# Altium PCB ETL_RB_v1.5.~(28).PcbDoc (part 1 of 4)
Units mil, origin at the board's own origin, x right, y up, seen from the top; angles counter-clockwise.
Board outline 5129.92 x 2224.41 mil, 8 copper layers (Top Layer, plane 1, M1, plane 2, plane 3, M2, plane 4, Bottom Layer), stack 36.907 mil thick; 212 components, 186 nets, 1961 pads, 978 vias.
Unrouted connection lines stored in the file: 395.
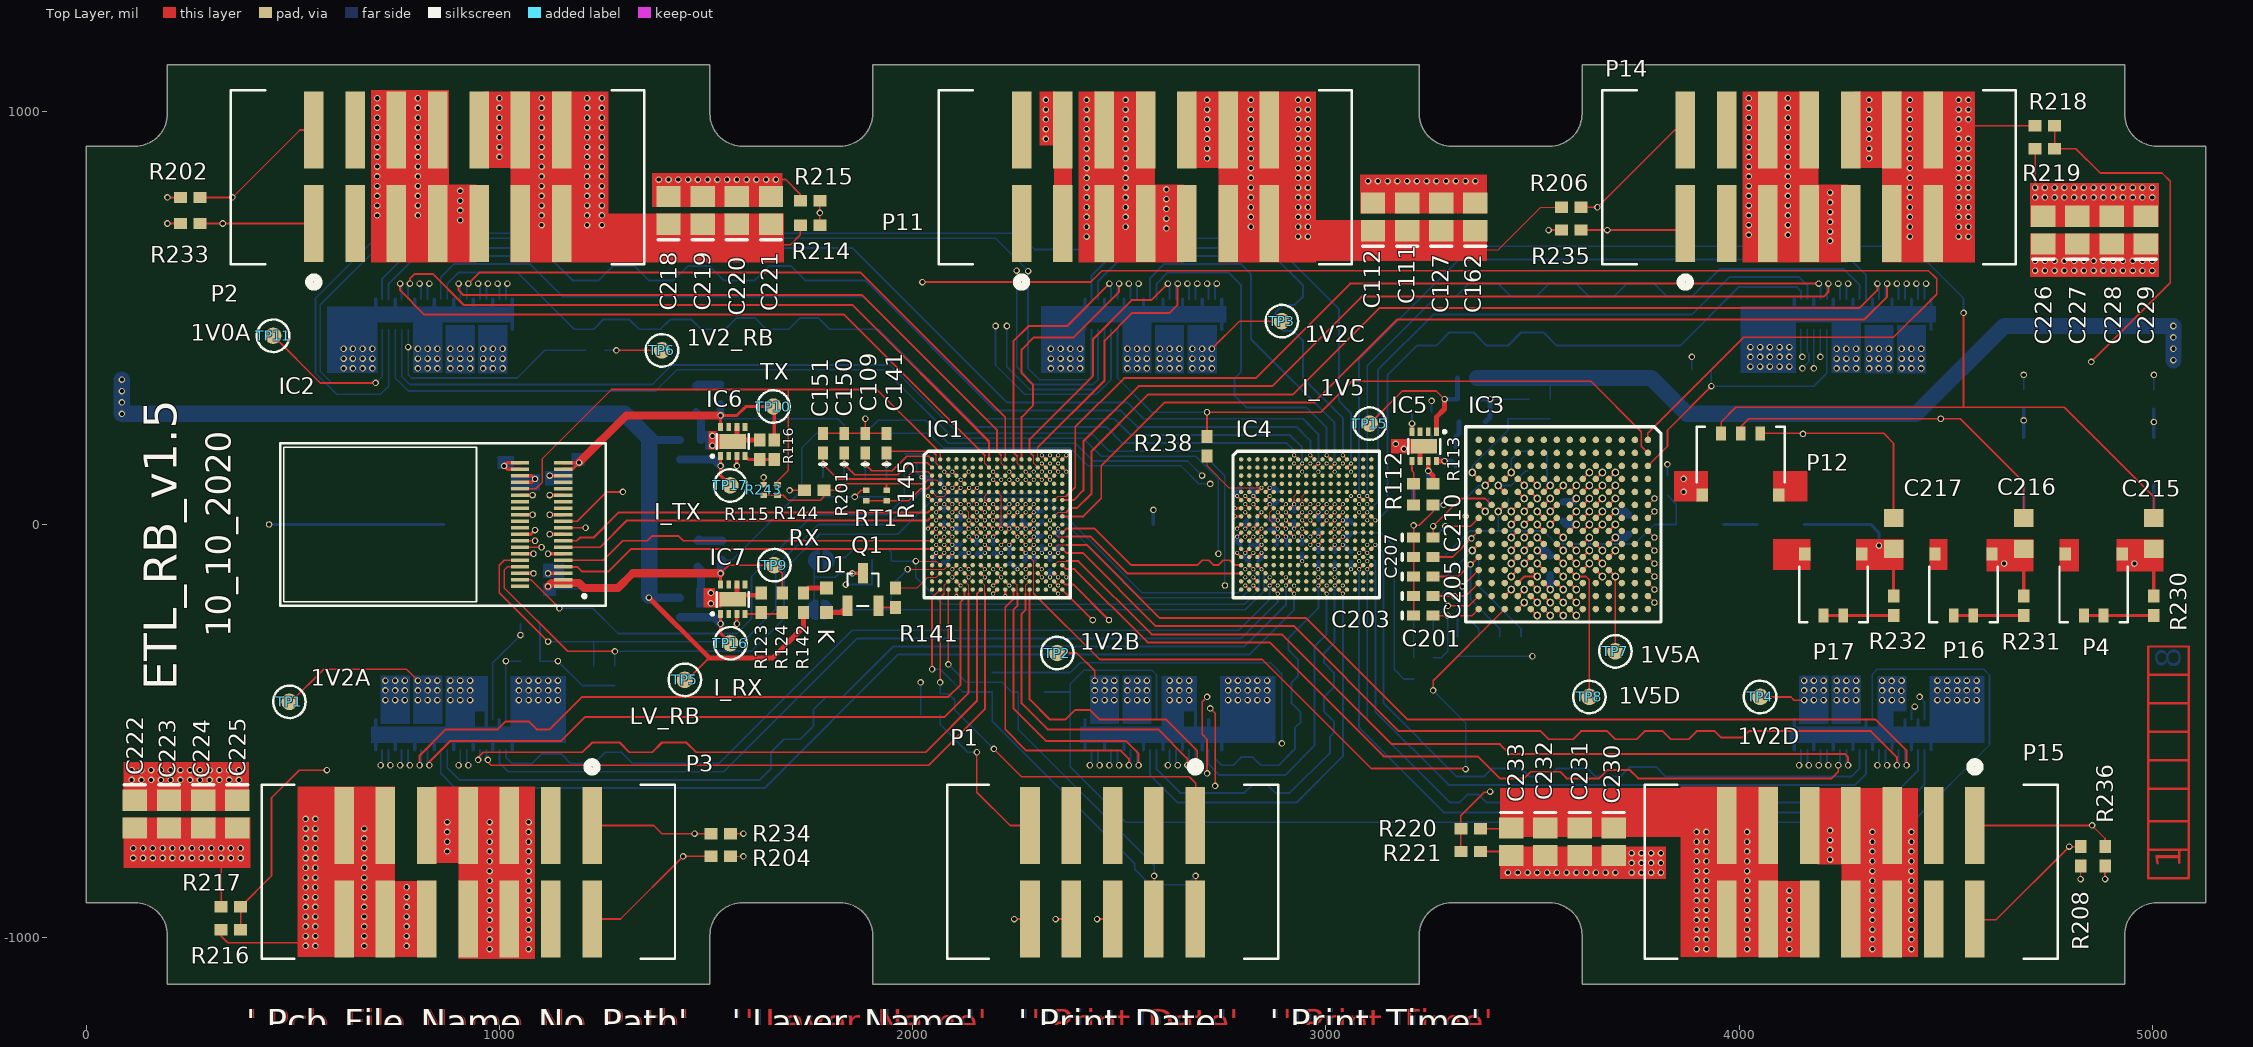
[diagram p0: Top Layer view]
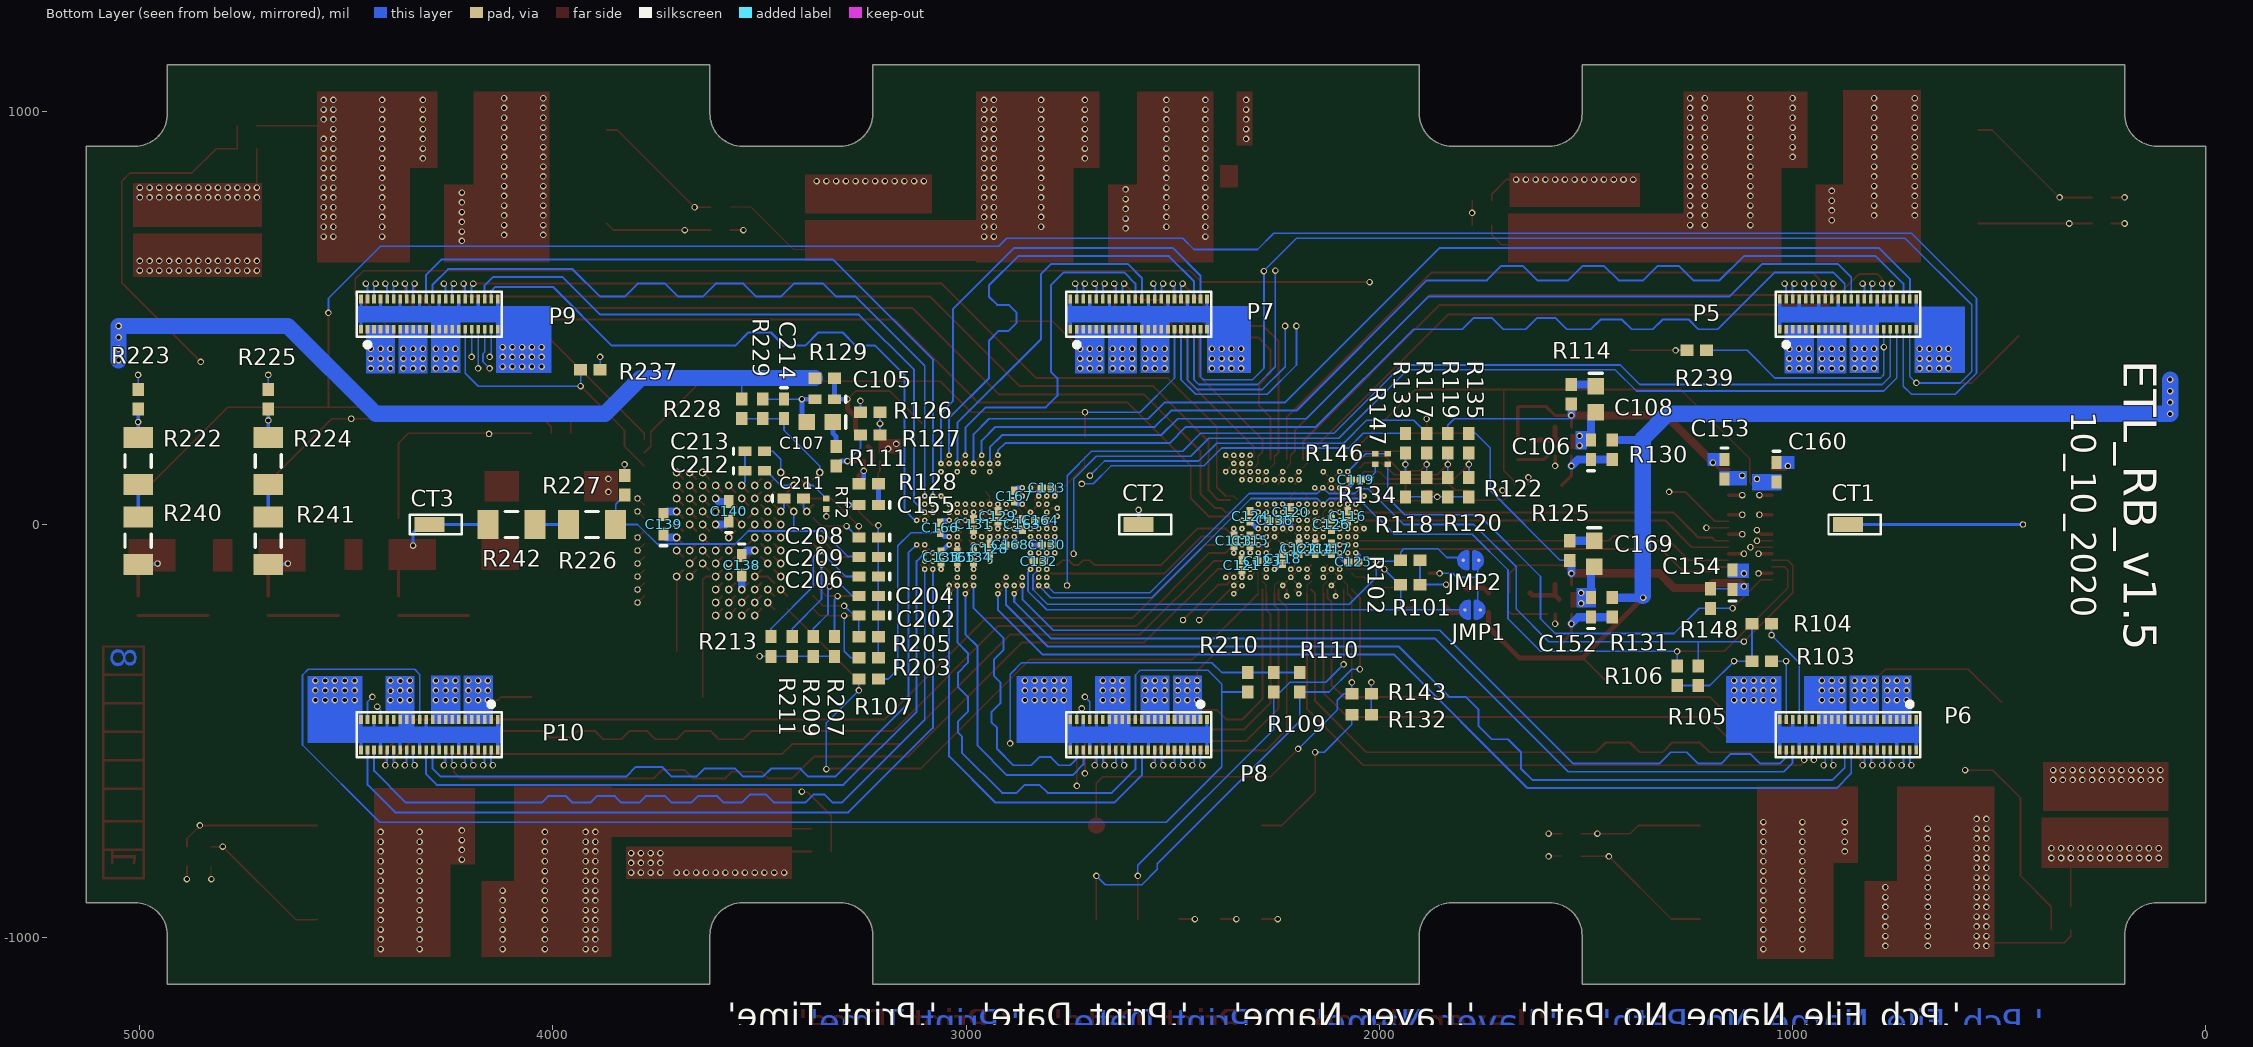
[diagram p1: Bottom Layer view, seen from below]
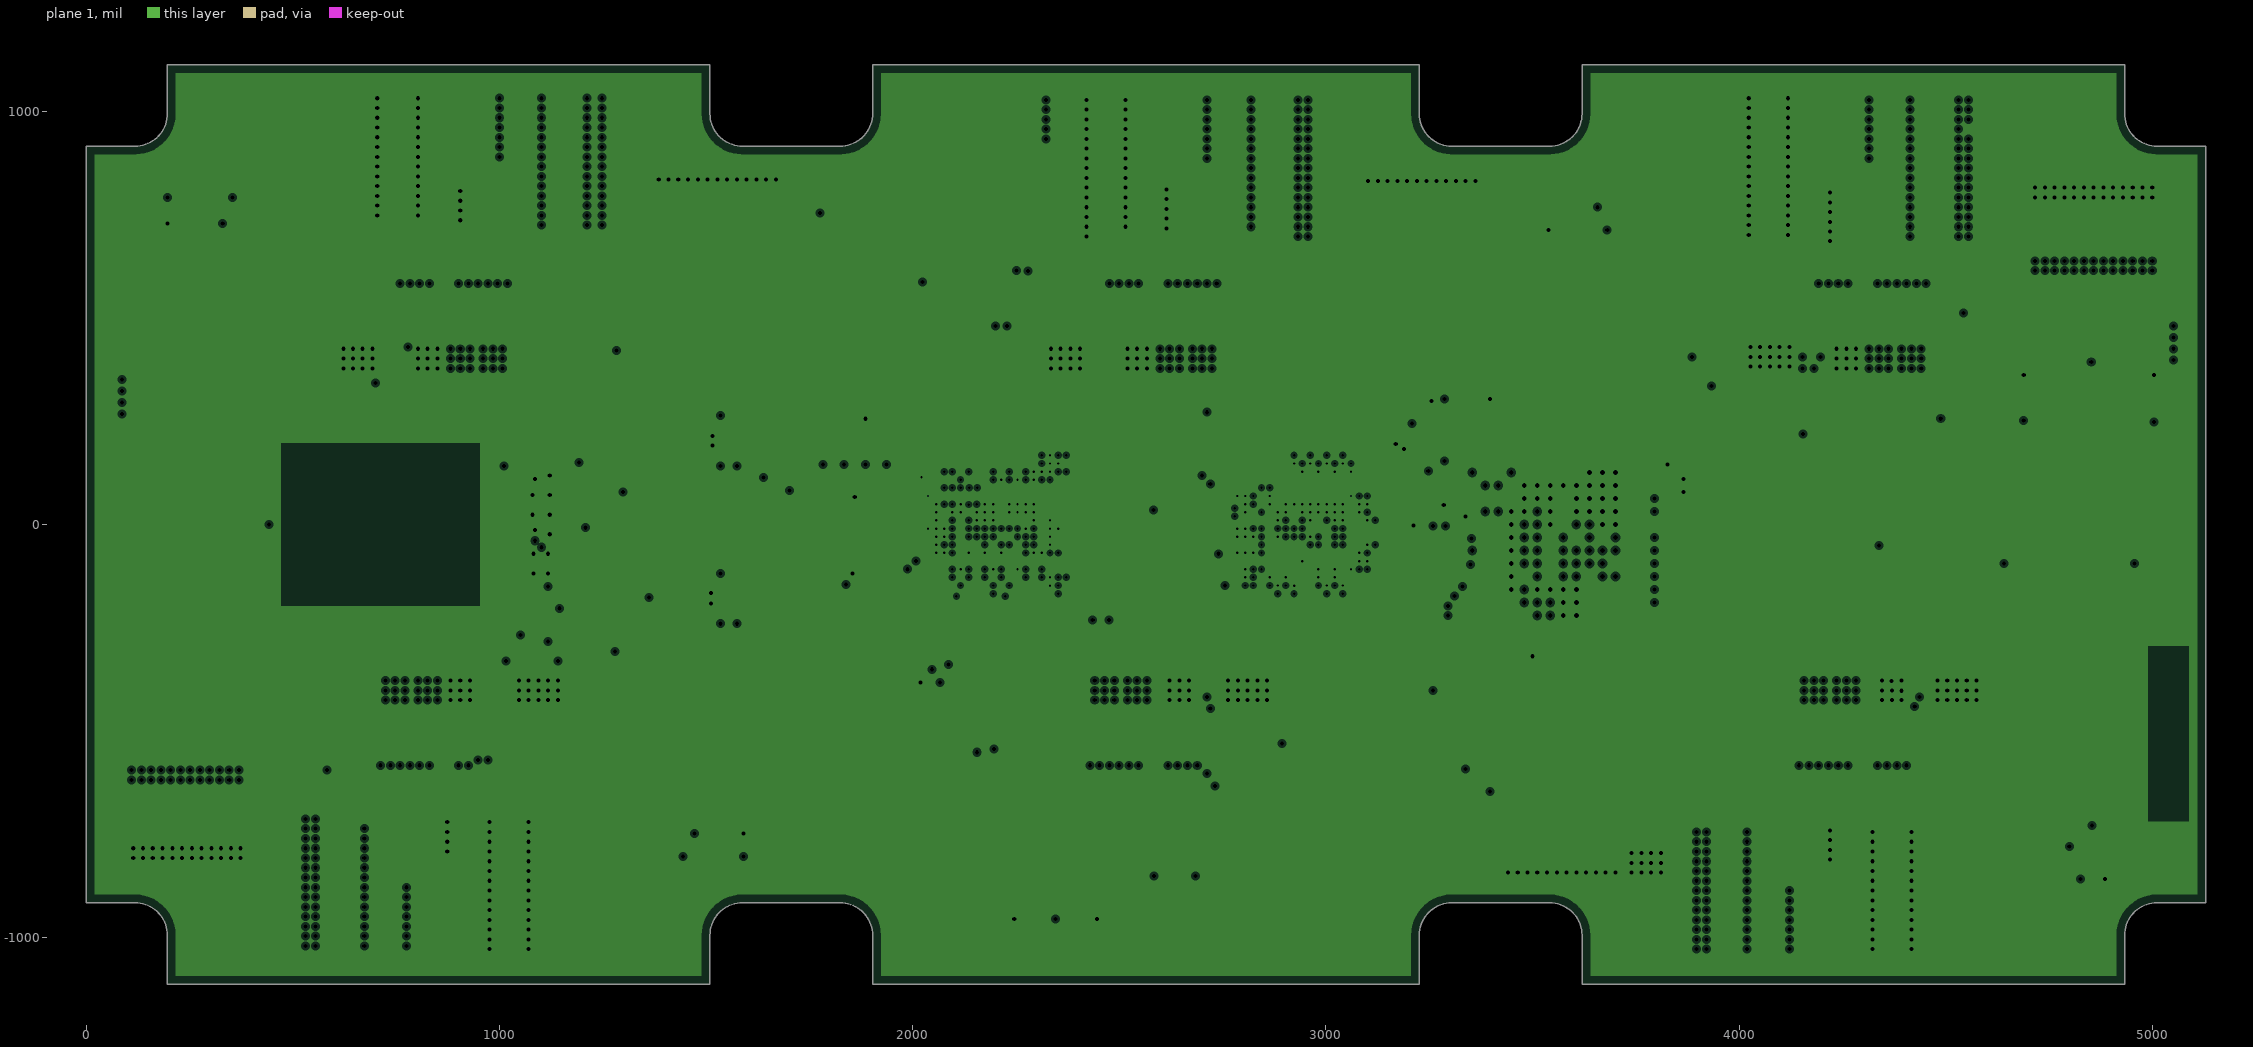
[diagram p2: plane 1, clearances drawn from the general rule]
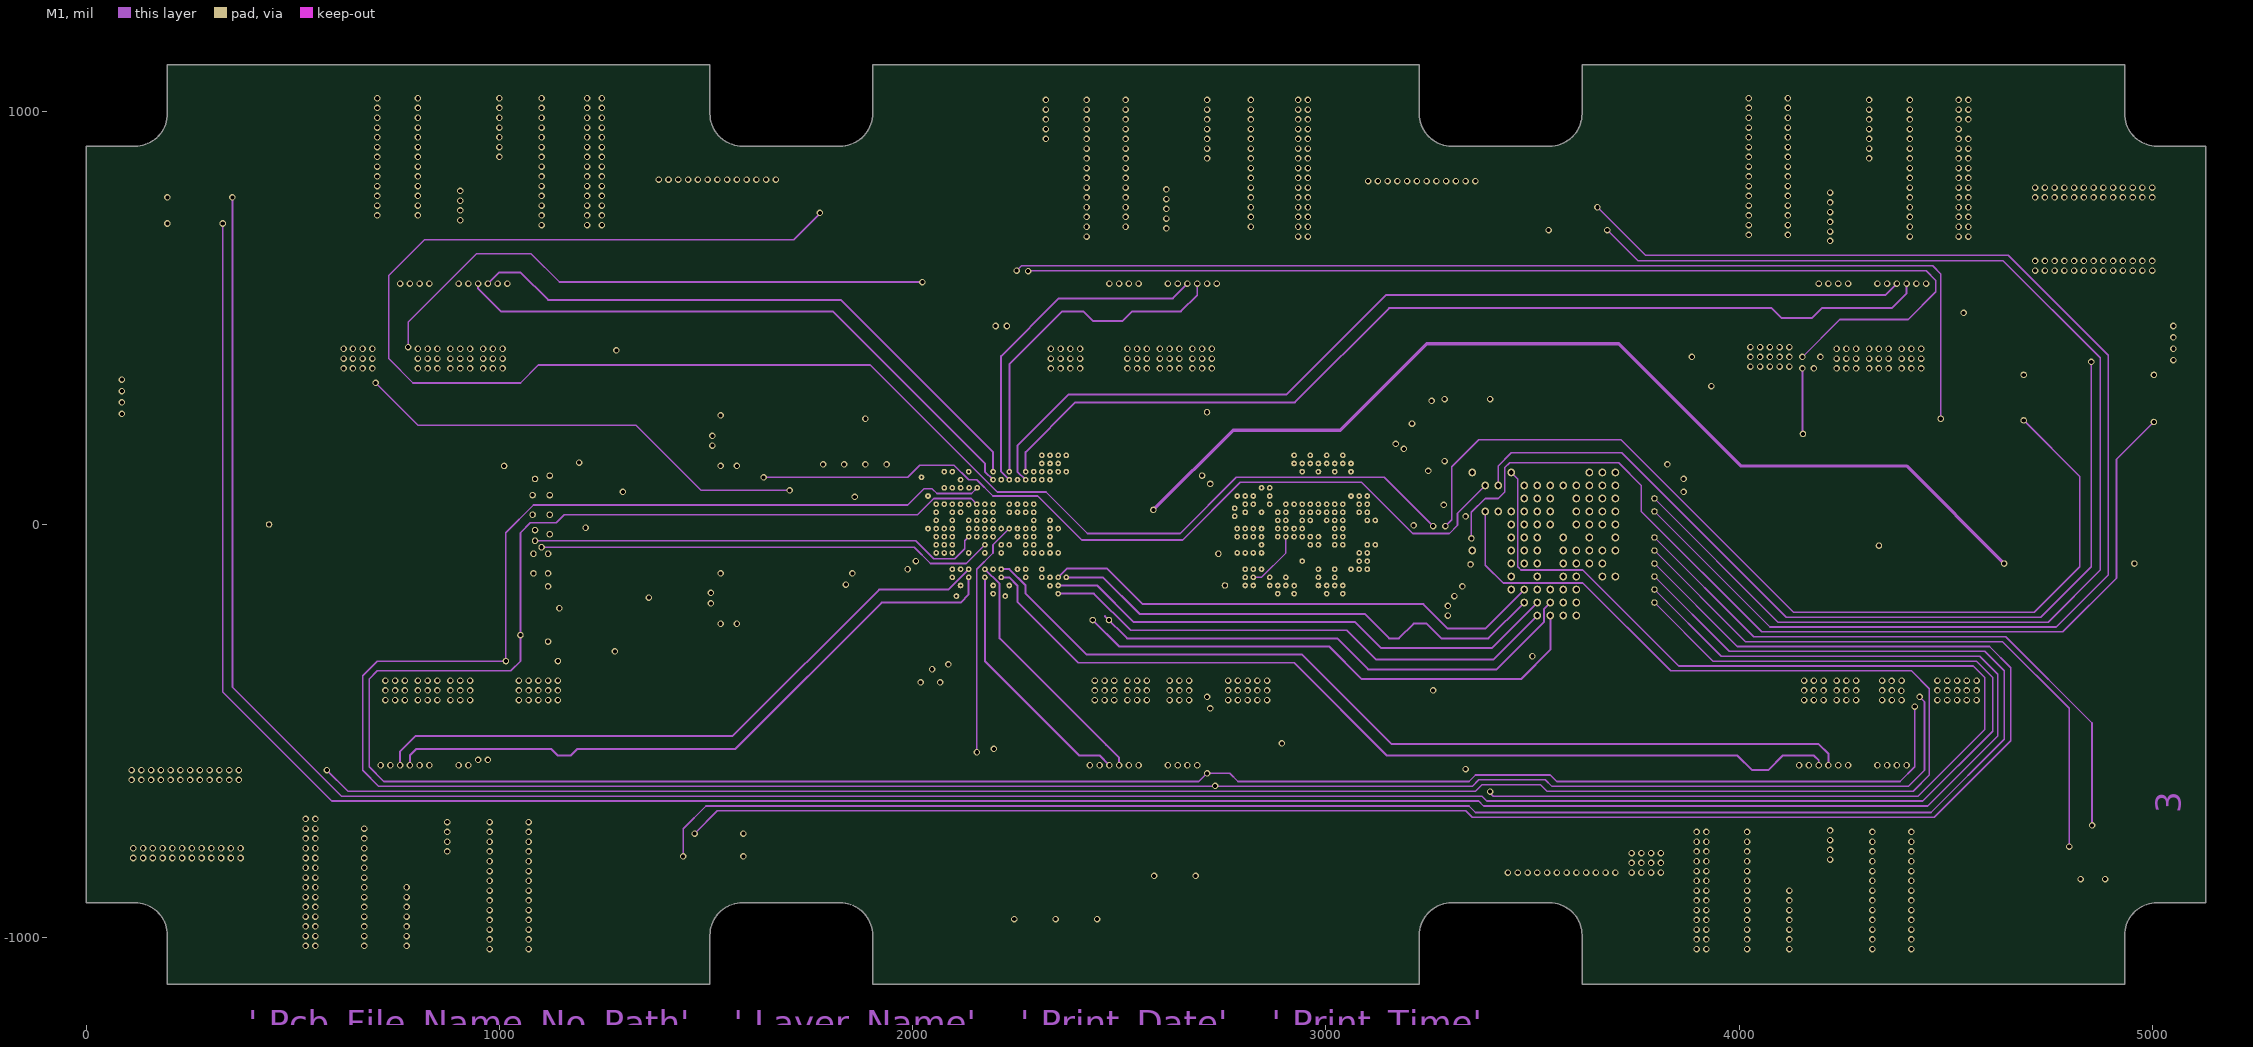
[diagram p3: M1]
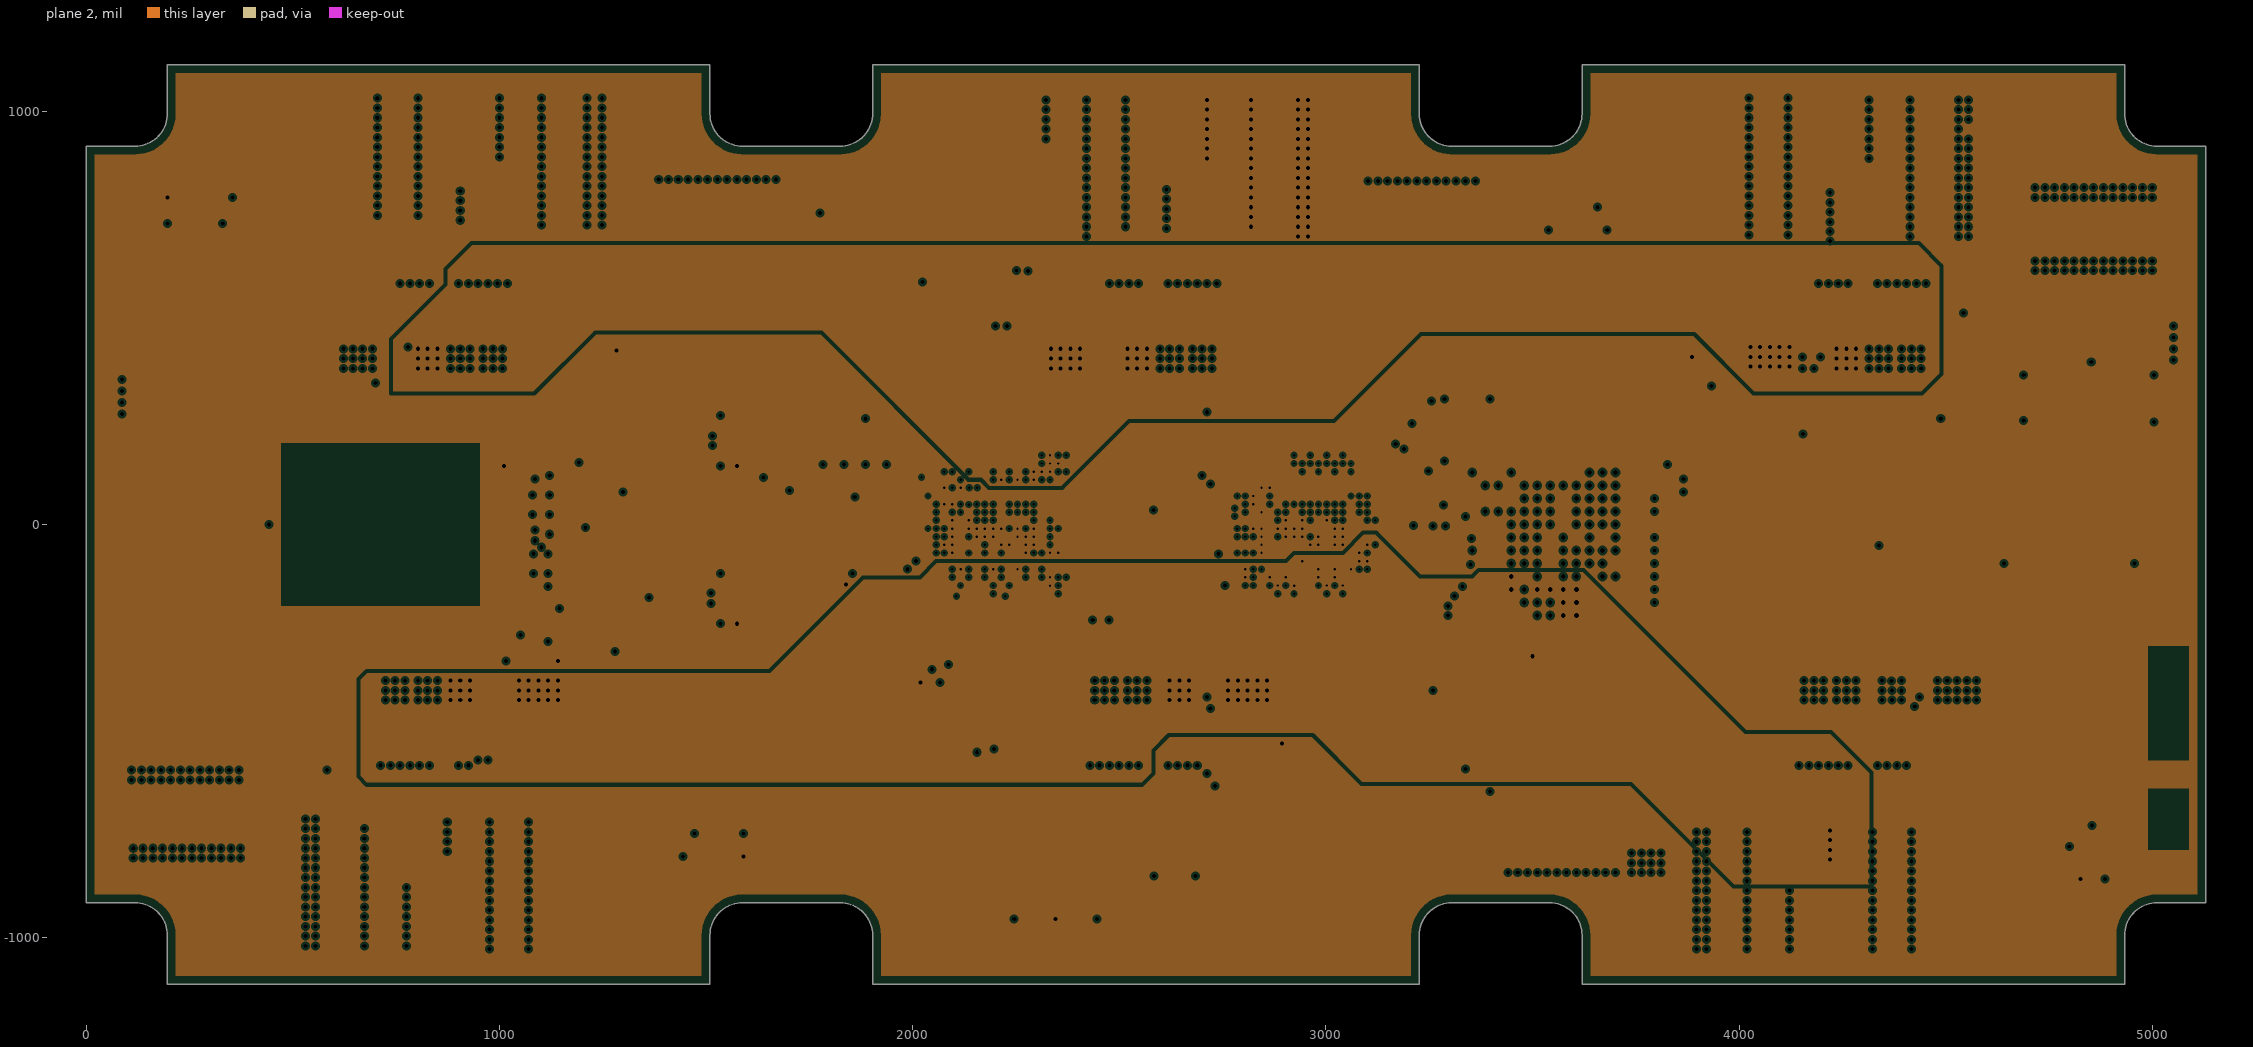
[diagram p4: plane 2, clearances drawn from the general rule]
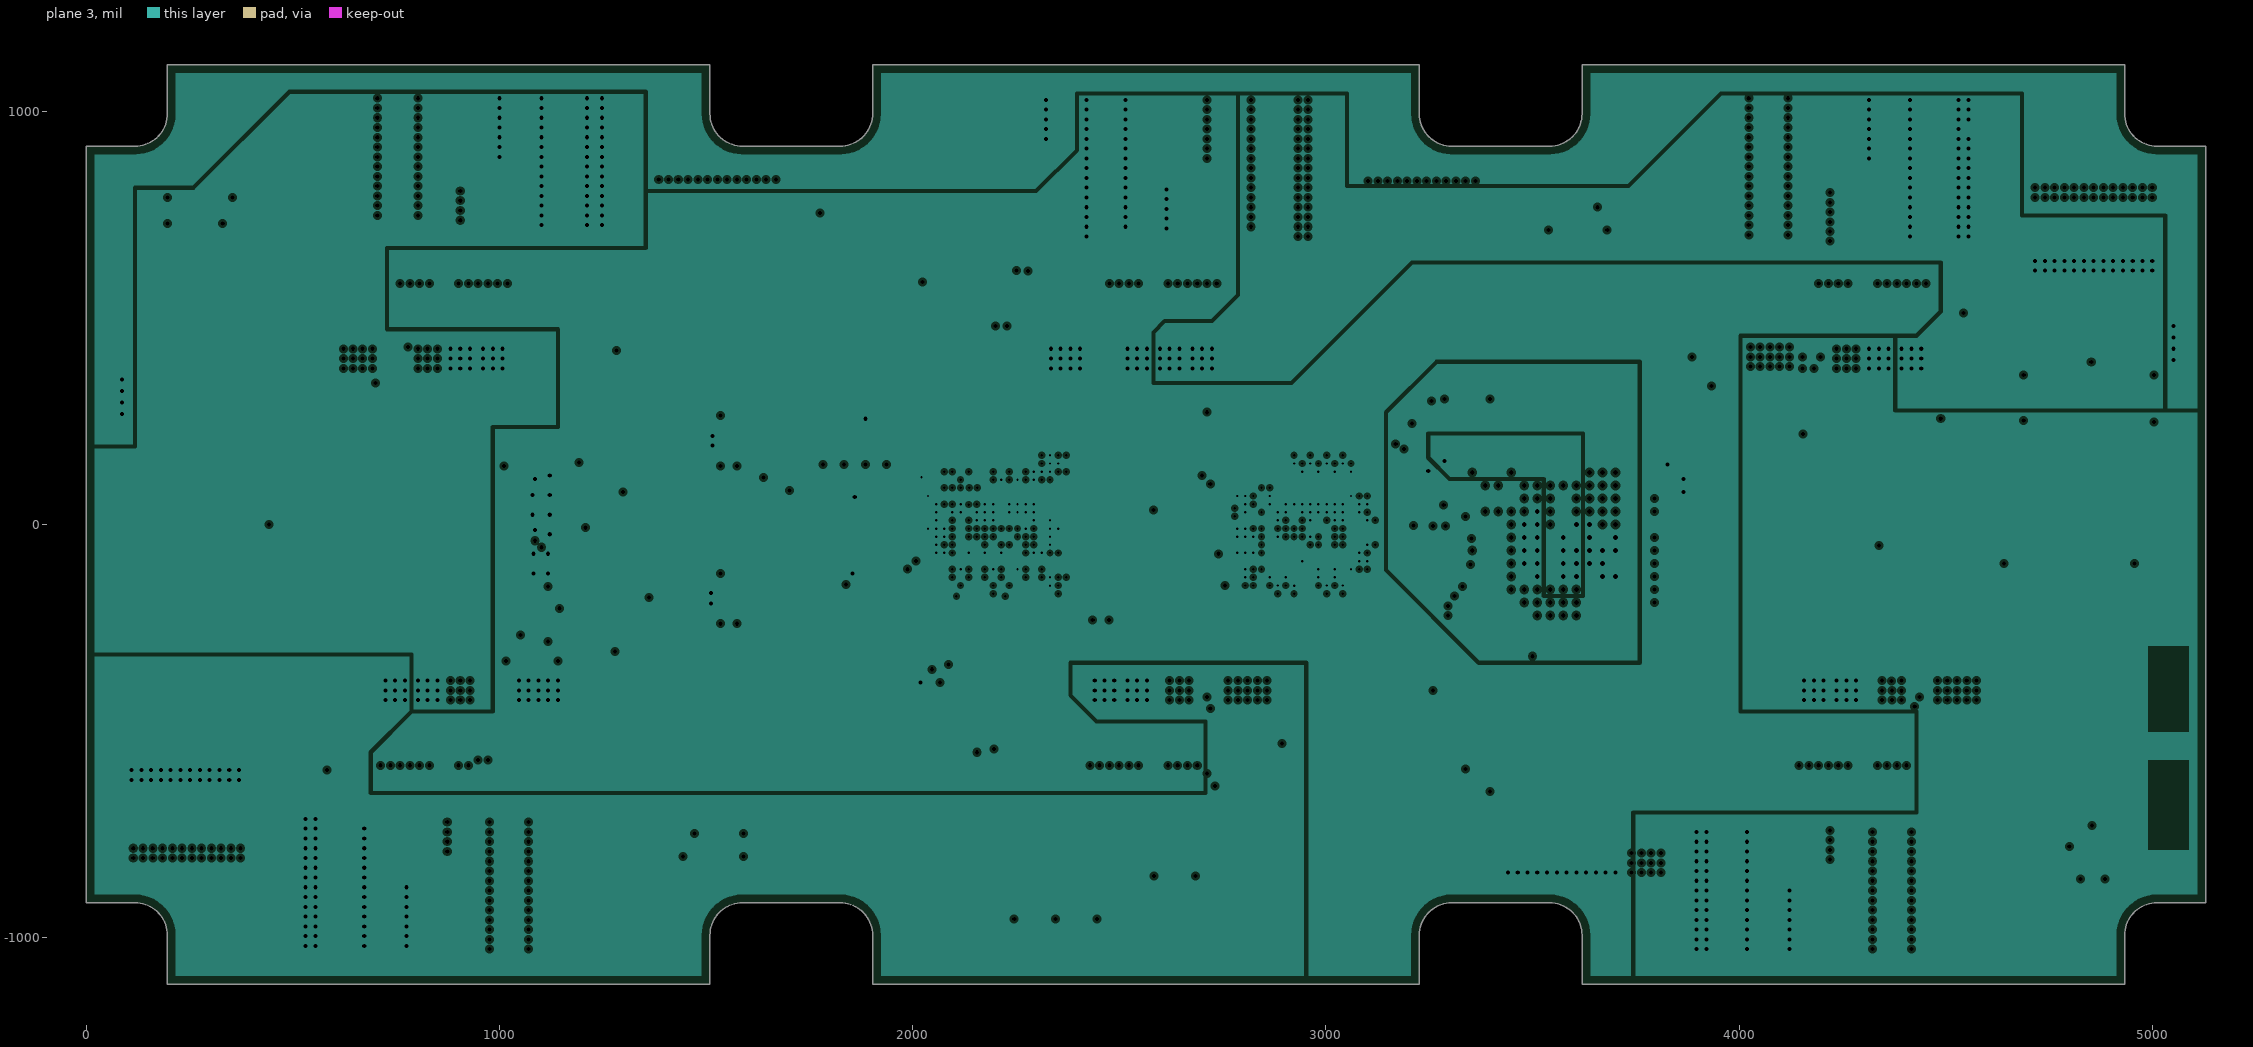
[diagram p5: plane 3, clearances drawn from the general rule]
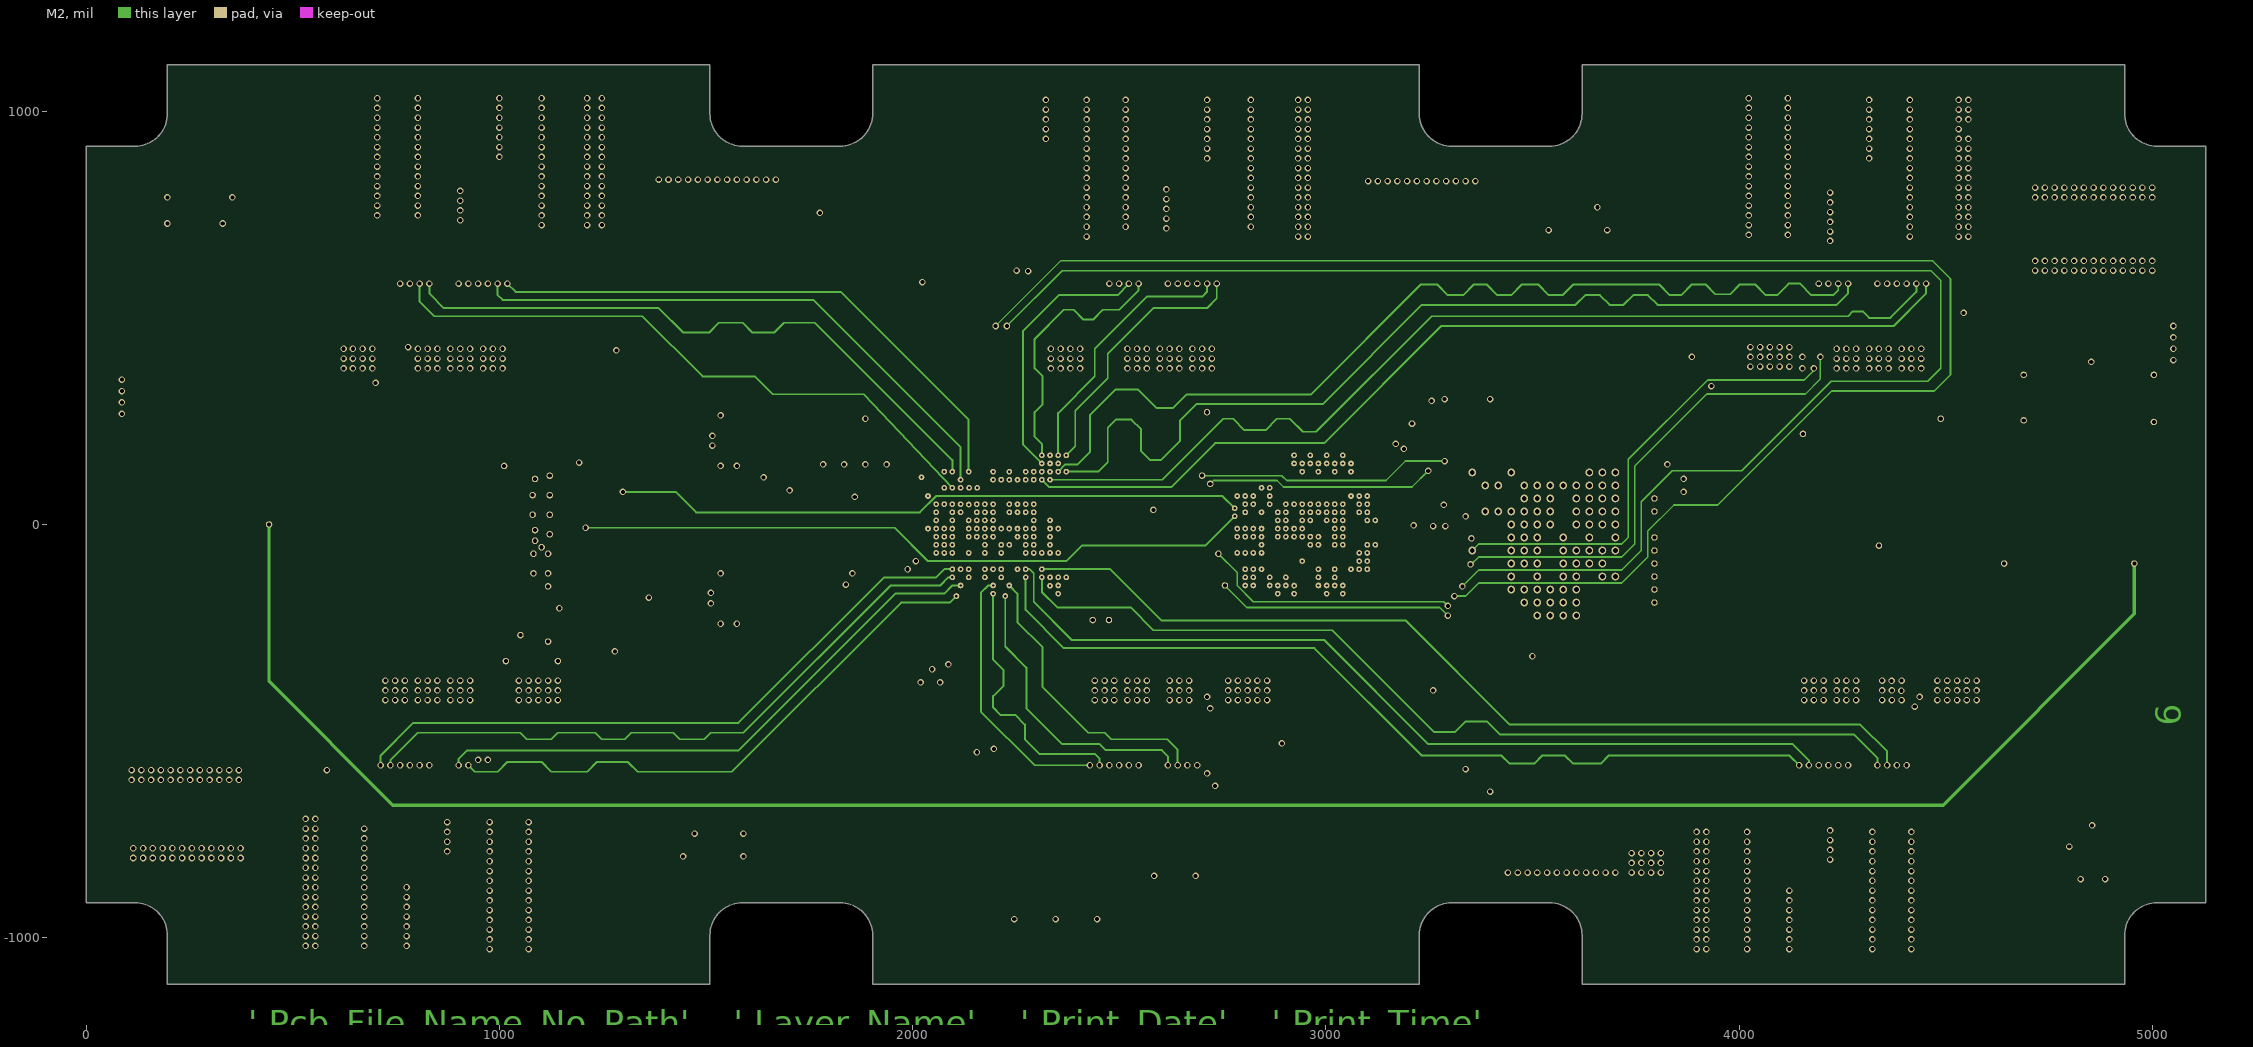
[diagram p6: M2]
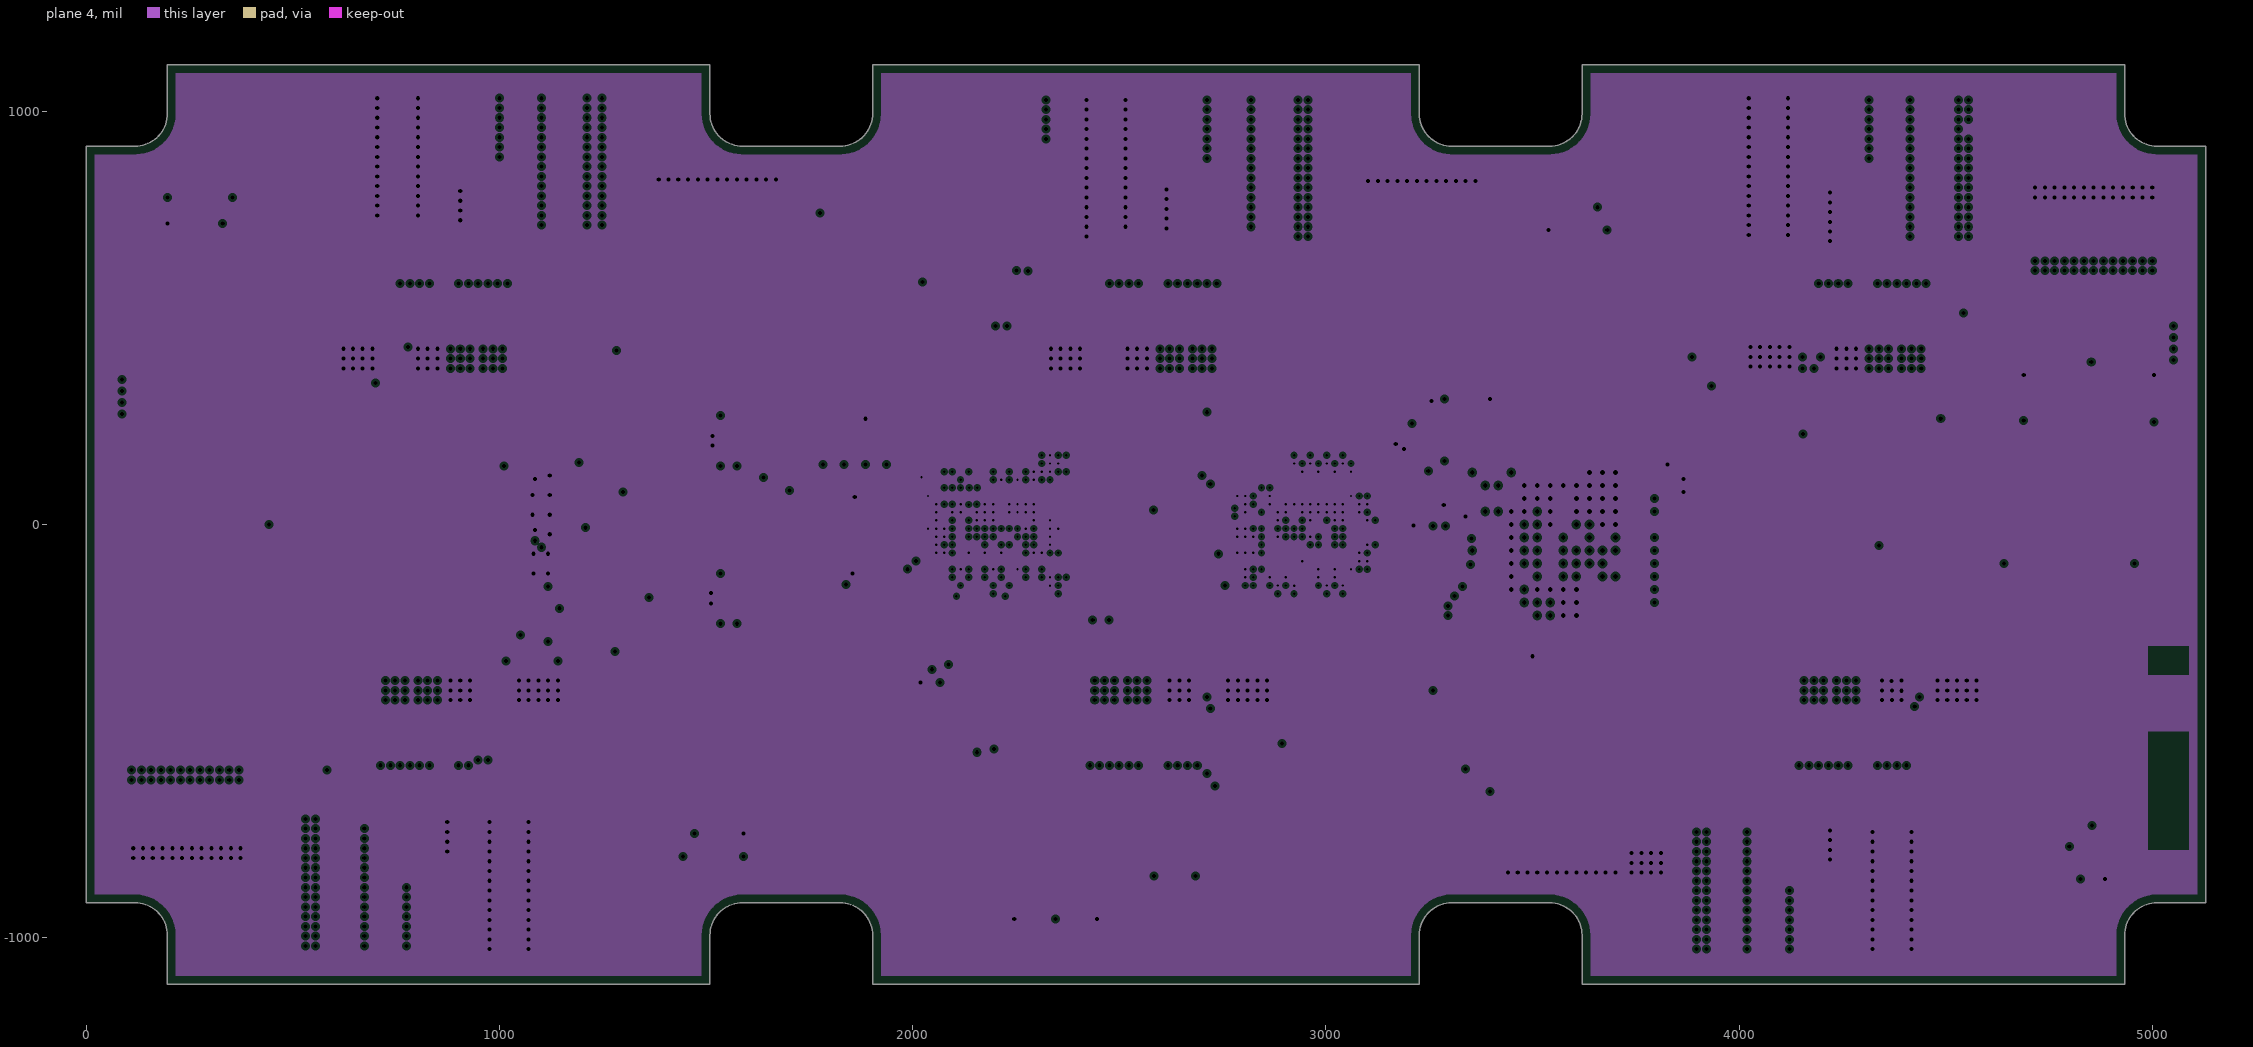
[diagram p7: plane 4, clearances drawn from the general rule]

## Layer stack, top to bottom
Top Solder: solder mask 0.7, Solder Resist, Dk 4.1
Top Layer: signal copper 0.689
Dielectric 1: prepreg 2.7201, 1080, Dk 3.4
plane 1: plane copper 1.378, net GND
Dielectric 2: core 4, TU-863, Dk 3.7
M1: signal copper 0.7087
Dielectric 3: prepreg 5.5799, 1080, Dk 3.4
plane 2: plane copper 1.378, net (Multiple Nets)
Dielectric 4: core 4, TU-863, Dk 3.7
plane 3: plane copper 1.378, net (Multiple Nets)
Dielectric 5: prepreg 5.5799, 1080, Dk 3.4
M2: signal copper 0.7087
Dielectric 6: core 4, TU-863, Dk 3.7
plane 4: plane copper 1.378, net GND
Dielectric 7: prepreg 2.7201, 1080, Dk 3.4
Bottom Layer: signal copper 0.689
Bottom Solder: solder mask 0.7, Solder Resist, Dk 4.1

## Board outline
196.85,-1112.2 196.85,-994.09 ccw(c118.11,-994.09) 118.11,-915.35 0,-915.35 0,915.35 118.11,915.35 ccw(c118.11,994.09) 196.85,994.09 196.85,1112.2 1509.84,1112.2 1509.84,994.09 ccw(c1588.58,994.09) 1588.58,915.35 1824.8,915.35 ccw(c1824.8,994.09) 1903.54,994.09 1903.54,1112.2 3226.38,1112.2 3226.38,994.09 ccw(c3305.12,994.09) 3305.12,915.35 3541.34,915.35 ccw(c3541.34,994.09) 3620.08,994.09 3620.08,1112.2 4933.07,1112.2 4933.07,994.09 ccw(c5011.81,994.09) 5011.81,915.35 5129.92,915.35 5129.92,-915.35 5011.81,-915.35 ccw(c5011.81,-994.09) 4933.07,-994.09 4933.07,-1112.2 3620.08,-1112.2 3620.08,-994.09 ccw(c3541.34,-994.09) 3541.34,-915.35 3305.12,-915.35 ccw(c3305.12,-994.09) 3226.38,-994.09 3226.38,-1112.2 1903.54,-1112.2 1903.54,-994.09 ccw(c1824.8,-994.09) 1824.8,-915.35 1588.58,-915.35 ccw(c1588.58,-994.09) 1509.84,-994.09 1509.84,-1112.2

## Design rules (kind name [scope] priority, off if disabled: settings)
Clearance [All] p1: gap=3 ignorepadtopadclearanceinfootprint=FALSE except(0: Arc-Hole Track-Hole SMDPad-Hole THPad-Hole Via-Hole Fill-Hole Poly-Hole Region-Hole Text-Hole)
Height [All] p1 off: minheight=0 maxheight=1000 prefheight=500
HoleToHoleClearance HoleToHoleClearance_1 [InNet('GND') or InNet('LV_RB') or InNet('1V5A') or InNet('1V5D') or InNet('1V2A') or InNet('1V2B') or InNet('1V2C') or InNet('1V2D') vs InNet('GND') or InNet('LV_RB') or InNet('1V5A') or InNet('1V5D') or InNet('1V2A') or InNet('1V2B') or InNet('1V2C') or InNet('1V2D')] p1: gap=5.91 allowstackedmicrovias=TRUE
HoleToHoleClearance [All] p2: gap=10 allowstackedmicrovias=TRUE
MinimumSolderMaskSliver [All] p1: minsoldermaskwidth=4
PlaneClearance PlaneClearance_1 [InNetClass('BV')] p1: clearance=20
PlaneClearance [All] p2: clearance=6
PlaneConnect PlaneConnect_1 [All] p1: planeconnectstyle=Direct reliefexpansion=20 reliefentries=4 reliefconductorwidth=10 reliefairgap=10
PolygonConnect [All] p1: connectstyle=Relief reliefconductorwidth=10 reliefentries=4 polygonreliefangle="90 Angle" airgapwidth=10
RoomDefinition WP7B [InComponentClass('WP7B')] p1 off: confinementstyle=ConfineIn formatcopy=TRUE lockcomponents=FALSE outline 7588.58,661.41 24163.39,661.41 24163.39,1842.52 7588.58,1842.52
RoomDefinition lpGBT [InComponentClass('lpGBT')] p2 off: confinementstyle=ConfineIn formatcopy=TRUE lockcomponents=FALSE outline 7559.06,-1446.85 41220.49,-1446.85 41220.49,-68.9 7559.06,-68.9
RoutingVias [All] p1: holewidth=9.84 width=15.75 viastyle="Through Hole" minholewidth=5.91 minwidth=9.84 maxholewidth=28 maxwidth=50
SilkToSilkClearance [All] p1: silktosilkclearance=0.98
SilkToSolderMaskClearance [IsPad] p1: minsilkscreentomaskgap=0.98 clearancetoexposedcopper=TRUE
SolderMaskExpansion SolderMaskExpansion_1 [InPadClass('WP7B40PAD')] p1: expansion=1.5 istentingtop=FALSE
SolderMaskExpansion [All] p2: expansion=2 istentingtop=FALSE
Width Width_HS [InNetClass('HS')] p1: maxlimit=5.12 minlimit=3 preferedwidth=4.72 midlayer1_minwidth=4.72 midlayer1_maxwidth=4.72 midlayer2_minwidth=4.72 midlayer2_maxwidth=4.72 bottomlayer_minwidth=4.72 bottomlayer_maxwidth=4.72 minimp=50.000000 maximp=50.000000 favimp=50.000000 // impedance controlled signals
Width [All] p2: maxlimit=100 minlimit=2.99 preferedwidth=4.72 toplayer_minwidth=3 midlayer1_minwidth=3 minimp=50.000000 maximp=50.000000 favimp=50.000000
23 further rules are at their usual default settings.

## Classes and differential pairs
pad class WP7B40PAD: IC2-1 IC2-2 IC2-3 IC2-4 IC2-5 IC2-6 IC2-7 IC2-8 IC2-9 IC2-10 IC2-11 IC2-12 IC2-13 IC2-14 IC2-15 IC2-16 IC2-17 IC2-18 IC2-19 IC2-20 IC2-21 IC2-22 IC2-23 IC2-24 IC2-25 IC2-26 IC2-27 IC2-28 IC2-29 IC2-30 IC2-31 IC2-32 IC2-33 IC2-34 IC2-35 IC2-36 IC2-37 IC2-38 IC2-39 IC2-40 IC5-1 IC5-2 IC5-3 IC5-4 IC5-5 IC5-6 IC5-7 IC5-8 IC5-9 IC6-1 IC6-2 IC6-3 IC6-4 IC6-5 IC6-6 IC6-7 IC6-8 IC6-9 IC7-1 IC7-2 IC7-3 IC7-4 IC7-5 IC7-6 IC7-7 IC7-8 IC7-9 P5-1 P5-2 P5-3 P5-4 P5-5 P5-6 P5-7 P5-8 P5-9 P5-10 P5-11 P5-12 P5-13 P5-14 P5-15 P5-16 P5-17 P5-18 P5-19 P5-20 P5-21 P5-22 P5-23 P5-24 P5-25 P5-26 P5-27 P5-28 P5-29 P5-30 P5-31 P5-32 P5-33 P5-34 P5-35 P5-36 P5-37 P5-38 P5-39 P5-40 P5-41 P5-42 P5-43 P5-44 P6-1 P6-2 P6-3 P6-4 P6-5 P6-6 P6-7 P6-8 P6-9 P6-10 P6-11 P6-12 P6-13 P6-14 P6-15 P6-16 P6-17 P6-18 P6-19 P6-20 P6-21 P6-22 P6-23 P6-24 P6-25 P6-26 P6-27 P6-28 P6-29 P6-30 P6-31 P6-32 P6-33 P6-34 P6-35 P6-36 P6-37 P6-38 P6-39 P6-40 P6-41 P6-42 P6-43 P6-44 P7-1 P7-2 P7-3 P7-4 P7-5 P7-6 P7-7 P7-8 P7-9 P7-10 P7-11 P7-12 P7-13 P7-14 P7-15 P7-16 P7-17 P7-18 P7-19 P7-20 P7-21 P7-22 P7-23 P7-24 P7-25 P7-26 P7-27 P7-28 P7-29 P7-30 P7-31 P7-32 P7-33 P7-34 P7-35 P7-36 P7-37 P7-38 P7-39 P7-40 P7-41 P7-42 P7-43 P7-44 P8-1 P8-2 P8-3 P8-4 P8-5 P8-6 P8-7 P8-8 P8-9 P8-10 P8-11 P8-12 P8-13 P8-14 P8-15 P8-16 P8-17 P8-18 P8-19 P8-20 P8-21 P8-22 P8-23 P8-24 P8-25 P8-26 P8-27 P8-28 P8-29 P8-30 P8-31 P8-32 P8-33 P8-34 P8-35 P8-36 P8-37 P8-38 P8-39 P8-40 P8-41 P8-42 P8-43 P8-44 P9-1 P9-2 P9-3 P9-4 P9-5 P9-6 P9-7 P9-8 P9-9 P9-10 P9-11 P9-12 P9-13 P9-14 P9-15 P9-16 P9-17 P9-18 P9-19 P9-20 P9-21 P9-22 P9-23 P9-24 P9-25 P9-26 P9-27 P9-28 P9-29 P9-30 P9-31 P9-32 P9-33 P9-34 P9-35 P9-36 P9-37 P9-38 P9-39 P9-40 P9-41 P9-42 P9-43 P9-44 P10-1 P10-2 P10-3 P10-4 P10-5 P10-6 P10-7 P10-8 P10-9 P10-10 P10-11 P10-12 P10-13 P10-14 P10-15 P10-16 P10-17 P10-18 P10-19 P10-20 P10-21 P10-22 P10-23 P10-24 P10-25 P10-26 P10-27 P10-28 P10-29 P10-30 P10-31 P10-32 P10-33 P10-34 P10-35 P10-36 P10-37 P10-38 P10-39 P10-40 P10-41 P10-42 P10-43 P10-44
component class WP7B40: P5 P6 P7 P8 P9 P10
component class WP7B: C201 C202 C203 C204 C205 C206 C207 C208 C209 C210 C211 C212 C213 C214 C215 C216 C217 C218 C219 C220 C221 C222 C223 C224 C225 C226 C227 C228 C229 C230 C231 C232 C233 CT1 CT2 CT3 P2 P3 P4 P5 P6 P7 P8 P9 P10 P12 P14 P15 P16 P17 R201 R202 R203 R204 R205 R206 R207 R208 R209 R210 R211 R213 R214 R215 R216 R217 R218 R219 R220 R221 R222 R223 R224 R225 R226 R227 R228 R229 R230 R231 R232 R233 R234 R235 R236 R237 R238 R239 R240 R241 R242 R243 RT2 TP1 TP2 TP3 TP4 TP5 TP6 TP7 TP8 TP9 TP10 TP11
component class lpGBT: C105 C106 C107 C108 C109 C111 C112 C113 C114 C115 C116 C117 C118 C119 C120 C121 C122 C123 C124 C125 C126 C127 C128 C129 C130 C131 C132 C133 C134 C135 C136 C138 C139 C140 C141 C150 C151 C152 C153 C154 C155 C160 C162 C163 C164 C165 C166 C167 C168 C169 D1 IC1 IC2 IC3 IC4 IC5 IC6 IC7 JMP1 JMP2 P1 P11 Q1 R101 R102 R103 R104 R105 R106 R107 R109 R110 R111 R112 R113 R114 R115 R116 R117 R118 R119 R120 R122 R123 R124 R125 R126 R127 R128 R129 R130 R131 R132 R133 R134 R135 R141 R142 R143 R144 R145 R146 R147 R148 RT1 TP15 TP16 TP17

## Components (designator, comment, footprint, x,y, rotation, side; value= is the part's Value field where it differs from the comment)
C105 "GRM155R71E104ME14D" capc1005n 3342.52,303.15 r0 bottom value=0.1uF
C106 "GRM155R71E104ME14D" capc1005n 1488.19,181.1 r90 bottom value=0.1uF
C107 "GRM185R60J106ME15J" CAPC1608N 3354.33,248.03 r0 bottom value=10uF
C108 "GRM185R60J106ME15J" CAPC1608N 1476.38,303.15 r270 bottom value=10uF
C109 "GRM155R71E104ME14D" capc1005n 1885.83,196.85 r90 top value=0.1uF
C111 "GRM188R60J476ME15D" capc2012n 3196.85,744.09 r90 top value=47uF
C112 "GRM188R60J476ME15D" capc2012n 3114.17,744.09 r90 top value=47uF
C113 "GRM033R61C104KE84D" CAPC0603N 2352.36,-39.37 r90 bottom value=0.1uF
C114 "GRM033R61C104KE84D" CAPC0603N 2155.51,-59.06 r270 bottom value=0.1uF
C115 "GRM033R61C104KE84D" CAPC0603N 2312.99,-39.37 r270 bottom value=0.1uF
C116 "GRM033R61C104KE84D" CAPC0603N 2076.77,19.68 r270 bottom value=0.1uF
C117 "GRM033R61C104KE84D" CAPC0603N 2116.14,-59.06 r270 bottom value=0.1uF
C118 "GRM033R61C104KE84D" CAPC0603N 2234.25,-82.68 r270 bottom value=0.1uF
C119 "GRM033R61C104KE84D" CAPC0603N 2057.09,108.27 r180 bottom value=0.1uF
C120 "GRM033R61C104KE84D" CAPC0603N 2214.57,29.53 r90 bottom value=0.1uF
C121 "GRM033R61C104KE84D" CAPC0603N 2332.68,-98.43 r270 bottom value=0.1uF
C122 "GRM033R61C153KE84D" CAPC0603N 2194.88,-59.06 r270 bottom value=15nF
C123 "GRM033R61C153KE84D" CAPC0603N 2283.46,-88.58 r0 bottom value=15nF
C124 "GRM033R61C153KE84D" CAPC0603N 2312.99,19.68 r90 bottom value=15nF
C125 "GRM033R61C153KE84D" CAPC0603N 2062.99,-90.55 r180 bottom value=15nF
C126 "GRM033R61C153KE84D" CAPC0603N 2116.14,0 r90 bottom value=15nF
C127 "GRM188R60J476ME15D" capc2012n 3279.53,744.09 r90 top value=47uF
C128 "GRM033R61C104KE84D" CAPC0603N 2942.91,-59.06 r270 bottom value=0.1uF
C129 "GRM033R61C104KE84D" CAPC0603N 2923.23,19.68 r90 bottom value=0.1uF
C130 "GRM033R61C104KE84D" CAPC0603N 2805.12,-49.21 r180 bottom value=0.1uF
C131 "GRM033R61C104KE84D" CAPC0603N 2982.28,0 r90 bottom value=0.1uF
C132 "GRM033R61C104KE84D" CAPC0603N 2824.8,-88.58 r180 bottom value=0.1uF
C133 "GRM033R61C104KE84D" CAPC0603N 2805.12,88.58 r180 bottom value=0.1uF
C134 "GRM033R61C104KE84D" CAPC0603N 2982.28,-78.74 r270 bottom value=0.1uF
C135 "GRM033R61C104KE84D" CAPC0603N 3061.02,-78.74 r270 bottom value=0.1uF
C136 "GRM033R61C104KE84D" CAPC0603N 2253.94,9.84 r0 bottom value=0.1uF
C138 "GRM155R71E104ME14D" capc1005n 3543.31,-98.43 r270 bottom value=0.1uF
C139 "GRM155R71E104ME14D" capc1005n 3732.28,0 r90 bottom value=0.1uF
C140 "GRM155R71E104ME14D" capc1005n 3574.8,31.5 r90 bottom value=0.1uF
C141 "GRM155R71E104ME14D" capc1005n 1937.01,196.85 r90 top value=0.1uF
C150 "GRM155R71E104ME14D" capc1005n 1834.65,196.85 r90 top value=0.1uF
C151 "GRM155R71E104ME14D" capc1005n 1783.46,196.85 r90 top value=0.1uF
C152 "GRM155R71E104ME14D" capc1005n 1488.19,-200.79 r90 bottom value=0.1uF
C153 "GRM155R71E104ME14D" capc1005n 1165.35,133.86 r270 bottom value=0.1uF
C154 "GRM155R71E104ME14D" capc1005n 1145.67,-133.86 r90 bottom value=0.1uF
C155 "GRM153R60J475ME15D" capc1005n 3236.22,47.24 r0 bottom value=4.7uF
C160 "GRM155R71E104ME14D" CAPC1005N 1039.37,125.98 r270 bottom value=0.1uF
C162 "GRM188R60J476ME15D" capc2012n 3362.2,744.09 r90 top value=47uF
C163 "GRM033R61C104KE84D" CAPC0603N 2864.17,0 r90 bottom value=0.1uF
C164 "GRM033R61C153KE84D" CAPC0603N 2820.87,9.84 r180 bottom value=15nF
C165 "GRM033R61C153KE84D" CAPC0603N 3021.65,-78.74 r270 bottom value=15nF
C166 "GRM033R61C153KE84D" CAPC0603N 3062.99,-7.87 r90 bottom value=15nF
C167 "GRM033R61C153KE84D" CAPC0603N 2883.86,68.9 r270 bottom value=15nF
C168 "GRM033R61C153KE84D" CAPC0603N 2893.7,-49.21 r180 bottom value=15nF
C169 "GRM185R60J106ME15J" CAPC1608N 1480.31,-70.87 r270 bottom value=10uF
C201 "GRM155R71E104ME14D" capc1005n 3236.22,-220.47 r0 top value=0.1uF
C202 "GRM155R71E104ME14D" capc1005n 3236.22,-220.47 r0 bottom value=0.1uF
C203 "GRM155R71E104ME14D" capc1005n 3236.22,-173.23 r0 top value=0.1uF
C204 "GRM155R71E104ME14D" capc1005n 3236.22,-173.23 r0 bottom value=0.1uF
C205 "GRM155R71E104ME14D" capc1005n 3236.22,-125.98 r0 top value=0.1uF
C206 "GRM155R71E104ME14D" capc1005n 3236.22,-125.98 r0 bottom value=0.1uF
C207 "GRM155R71E104ME14D" capc1005n 3236.22,-78.74 r0 top value=0.1uF
C208 "GRM155R71E104ME14D" capc1005n 3236.22,-31.5 r0 bottom value=0.1uF
C209 "GRM155R71E104ME14D" capc1005n 3236.22,-78.74 r0 bottom value=0.1uF
C210 "GRM155R71E104ME14D" capc1005n 3236.22,-31.5 r0 top value=0.1uF
C211 "GRM155R71E104ME14D" capc1005n 3417.32,62.99 r180 bottom value=0.1uF
C212 "GRM155R71E104ME14D" capc1005n 3511.81,129.92 r180 bottom value=0.1uF
C213 "GRM155R71E104ME14D" capc1005n 3511.81,177.17 r180 bottom value=0.1uF
C214 "GRM155R71E104ME14D" capc1005n 3440.94,279.53 r270 bottom value=0.1uF
C215 "C0805X7R102-152MNE" VENKEL0805 5003.94,-59.06 r90 top value=1500pF
C216 "C0805X7R102-152MNE" VENKEL0805 4688.98,-59.06 r90 top value=1500pF
C217 "C0805X7R102-152MNE" VENKEL0805 4374.02,-59.06 r90 top value=1500pF
C218 "GRM188R60J476ME15D" capc2012n 1409.45,759.84 r90 top value=47uF
C219 "GRM188R60J476ME15D" capc2012n 1492.13,759.84 r90 top value=47uF
C220 "GRM188R60J476ME15D" capc2012n 1574.8,759.84 r90 top value=47uF
C221 "GRM188R60J476ME15D" capc2012n 1657.48,759.84 r90 top value=47uF
C222 "GRM188R60J476ME15D" capc2012n 118.11,-700.79 r270 top value=47uF
C223 "GRM188R60J476ME15D" capc2012n 200.79,-700.79 r270 top value=47uF
C224 "GRM188R60J476ME15D" capc2012n 283.46,-700.79 r270 top value=47uF
C225 "GRM188R60J476ME15D" capc2012n 366.14,-700.79 r270 top value=47uF
C226 "GRM188R60J476ME15D" capc2012n 4736.22,712.6 r90 top value=47uF
C227 "GRM188R60J476ME15D" capc2012n 4818.9,712.6 r90 top value=47uF
C228 "GRM188R60J476ME15D" capc2012n 4901.57,712.6 r90 top value=47uF
C229 "GRM188R60J476ME15D" capc2012n 4984.25,712.6 r90 top value=47uF
C230 "GRM188R60J476ME15D" capc2012n 3696.85,-767.72 r270 top value=47uF
C231 "GRM188R60J476ME15D" capc2012n 3614.17,-767.72 r270 top value=47uF
C232 "GRM188R60J476ME15D" capc2012n 3531.5,-767.72 r270 top value=47uF
C233 "GRM188R60J476ME15D" capc2012n 3448.82,-767.72 r270 top value=47uF
CT1 "TE1551631-5" CONTACT 866.14,0 r0 bottom locked
CT2 "TE1551631-5" CONTACT 2582.68,0 r0 bottom locked
CT3 "TE1551631-5" CONTACT 4299.21,0 r0 bottom locked
D1 "LTST-C191KGKT" LED_RED 1791.34,-153.54 r270 top
IC1 "LPGBT" BGA289X17 2047.24,157.48 r0 top
IC2 "DF40C-40DS-0.4V" VTRX+ 1154.72,-149.61 r90 top locked
IC3 "GBT-SCA" BGA196C80P14X14_1200X1200X170 3779.53,204.72 r270 top
IC4 "LPGBT" BGA289X17 2795.28,157.48 r0 top
IC5 "linPOL12V" WDFNX208 3267.72,224.41 r180 top
IC6 "linPOL12V" WDFNX208 1535.43,165.35 r0 top
IC7 "linPOL12V" WDFNX208 1535.43,-216.54 r0 top
JMP1 "Not a component, printed on PCB" JMP2PCB#1 1775.59,-206.69 r90 bottom
JMP2 "Not a component, printed on PCB" JMP2PCB#2 1779.53,-86.61 r90 bottom
P1 "CnC3020-10-0300-00" cnc10 2684.25,-728.35 r180 top
P2 "CnC3020-14-0300-00" cnc14 551.18,728.35 r0 top locked
P3 "CnC3020-14-0300-00" cnc14 1224.41,-728.35 r180 top locked
P4 "DF57-2P-1.2V(21)" DF57-2 4834.65,-220.47 r0 top
P5 "WP7B-P040VA1" WP7B-40P 1015.75,472.44 r180 bottom locked
P6 "WP7B-P040VA1" WP7B-40P 716.54,-472.44 r0 bottom locked
P7 "WP7B-P040VA1" WP7B-40P 2732.28,472.44 r180 bottom locked
P8 "WP7B-P040VA1" WP7B-40P 2433.07,-472.44 r0 bottom locked
P9 "WP7B-P040VA1" WP7B-40P 4448.82,472.44 r180 bottom locked
P10 "WP7B-P040VA1" WP7B-40P 4149.61,-472.44 r0 bottom locked
P11 "CnC3020-14-0300-00" cnc14 2263.78,728.35 r0 top locked
P12 "DF57-3P-1.2V(21)" DF57-3 4051.18,220.47 r180 top
P14 "CnC3020-14-0300-00" cnc14 3870.08,728.35 r0 top locked
P15 "CnC3020-14-0300-00" cnc14 4570.87,-728.35 r180 top locked
P16 "DF57-2P-1.2V(21)" DF57-2 4519.69,-220.47 r0 top
P17 "DF57-2P-1.2V(21)" DF57-2 4204.72,-220.47 r0 top
Q1 "KSC2223YMTF" SOT-23 1842.52,-196.85 r0 top
R101 "ERJ-2GEJ392X" resc1005n 1925.2,-145.67 r180 bottom
R102 "ERJ-2GEJ392X" resc1005n 1925.2,-86.61 r0 bottom
R103 "ERJ-2GEJ202X" resc1005n 1074.8,-330.71 r0 bottom
R104 "ERJ-2GEJ202X" resc1005n 1074.8,-240.16 r0 bottom
R105 "ERJ-2GEJ392X" resc1005n 1228.35,-366.14 r270 bottom
R106 "ERJ-2GEJ392X" resc1005n 1279.53,-366.14 r270 bottom
R107 "ERJ-2GEJ392X" resc1005n 3236.22,-374.02 r0 bottom
R109 "ERJ-2GEJ392X" resc1005n 2255.91,-381.89 r90 bottom
R110 "ERJ-2GEJ392X" resc1005n 2192.91,-381.89 r90 bottom
R111 "ERJ-2BQJR30X" resc1005n 3314.96,165.35 r90 bottom
R112 "RR0510P-4020-D" resc1005n 3236.22,47.24 r0 top
R113 "RR0510P-6040-D" resc1005n 3236.22,98.43 r180 top
R114 "ERJ-2BQJR30X" resc1005n 1535.43,314.96 r270 bottom
R115 "RR0510P-4870-D" resc1005n 1629.92,181.1 r90 top
R116 "RR0510P-1541-D" resc1005n 1665.35,181.1 r270 top
R117 "RR0510P-152-D" resc1005n 1885.83,196.85 r90 bottom
R118 "RR0510P-202-D" resc1005n 1885.83,90.55 r90 bottom
R119 "RR0510P-302-D" resc1005n 1834.65,196.85 r90 bottom
R120 "RR0510P-152-D" resc1005n 1834.65,90.55 r90 bottom
R122 "RR0510P-152-D" resc1005n 1783.46,90.55 r90 bottom
R123 "RR0510P-4870-D" resc1005n 1633.86,-188.98 r90 top
R124 "RR0510P-1541-D" resc1005n 1685.04,-188.98 r270 top
R125 "ERJ-2BQJR30X" resc1005n 1539.37,-62.99 r270 bottom
R126 "RR0510P-4020-D" resc1005n 3232.28,271.65 r0 bottom
R127 "RR0510P-6040-D" resc1005n 3232.28,216.54 r180 bottom
R128 "ERJ-2BQJR30X" resc1005n 3236.22,98.43 r180 bottom
R129 "ERJ-2GEJ5R1X" resc1005n 3342.52,354.33 r180 bottom
R130 "ERJ-2GEJ5R1X" resc1005n 1437.01,181.1 r270 bottom
R131 "ERJ-2GEJ5R1X" resc1005n 1437.01,-200.79 r270 bottom
R132 "ERJ-2GEJ392X" resc1005n 2043.31,-460.63 r180 bottom
R133 "RR0510P-152-D" resc1005n 1937.01,196.85 r90 bottom
R134 "RR0510P-202-D" resc1005n 1937.01,90.55 r90 bottom
R135 "RR0510P-302-D" resc1005n 1783.46,196.85 r90 bottom
R141 "ERJ-2GEJ511X" resc1005n 1958.66,-177.17 r270 top
R142 "ERJ-2GEJ102X" resc1005n 1736.22,-188.98 r90 top
R143 "ERJ-2GEJ392X" resc1005n 2043.31,-409.45 r0 bottom
R144 "ERJ-1GNF-1002C" RESC0603 1673.23,96.46 r270 top
R145 "ERJ-1GNF-1002C" resc0603 1937.01,57.09 r90 top
R146 "ERJ-1GEF4023C" resc0603 2009.84,145.67 r90 bottom
R147 "ERJ-1GNF1004C" resc0603 1980.31,171.26 r270 bottom
R148 "ERJ-2RKF4751X" resc1005n 1198.82,-179.13 r90 bottom
R201 "ERJ-2GEJ201X" resc1005n 1761.81,82.68 r0 top
R202 "ERJ-2GEJ392X" resc1005n 251.97,791.34 r180 top
R203 "RR0510P-302-D" resc1005n 3236.22,-322.83 r0 bottom
R204 "ERJ-2GEJ392X" resc1005n 1535.43,-803.15 r0 top
R205 "RR0510P-302-D" resc1005n 3236.22,-271.65 r0 bottom
R206 "ERJ-2GEJ392X" resc1005n 3594.49,767.72 r180 top
R207 "RR0510P-302-D" resc1005n 3318.9,-295.28 r90 bottom
R208 "ERJ-2GEJ392X" resc1005n 4826.77,-803.15 r270 top
R209 "RR0510P-302-D" resc1005n 3370.08,-295.28 r90 bottom
R210 "ERJ-2GEJ392X" resc1005n 2318.9,-381.89 r90 bottom
R211 "RR0510P-302-D" resc1005n 3421.26,-295.28 r90 bottom
R213 "RR0510P-302-D" resc1005n 3472.44,-295.28 r90 bottom
R214 "RR0510P-122-D" resc1005n 1751.97,724.41 r180 top
R215 "RR0510P-302-D" resc1005n 1751.97,783.46 r0 top
R216 "RR0510P-122-D" resc1005n 350.39,-980.32 r180 top
R217 "RR0510P-302-D" resc1005n 350.39,-925.2 r0 top
R218 "RR0510P-122-D" resc1005n 4740.16,964.57 r180 top
R219 "RR0510P-302-D" resc1005n 4740.16,909.45 r0 top
R220 "RR0510P-122-D" resc1005n 3350.39,-736.22 r0 top
R221 "RR0510P-302-D" resc1005n 3350.39,-791.34 r180 top
R222 "HVC1206T5005JET" RESC3216N 5003.94,153.54 r270 bottom
R223 "RR0510P-823-D" resc1005n 5003.94,303.15 r270 bottom
R224 "HVC1206T5005JET" RESC3216N 4688.98,153.54 r270 bottom
R225 "RR0510P-823-D" resc1005n 4688.98,303.15 r270 bottom
R226 "HVC1206T5005JET" RESC3216N 3905.51,0 r0 bottom
R227 "RR0510P-823-D" resc1005n 3826.77,94.49 r270 bottom
R228 "RR0510P-103-D" resc1005n 3543.31,279.53 r90 bottom
R229 "RR0510P-102-D" resc1005n 3492.13,279.53 r270 bottom
R230 "ERJ-2GEJ201X" resc1005n 5003.94,-196.85 r270 top
R231 "ERJ-2GEJ201X" resc1005n 4688.98,-196.85 r270 top
R232 "ERJ-2GEJ201X" resc1005n 4374.02,-196.85 r270 top
R233 "ERJ-2GEJ392X" resc1005n 251.97,728.35 r180 top
R234 "ERJ-2GEJ392X" resc1005n 1535.43,-748.03 r0 top
R235 "ERJ-2GEJ392X" resc1005n 3594.49,712.6 r180 top
R236 "ERJ-2GEJ392X" resc1005n 4885.83,-803.15 r270 top
R237 "ERJ-2GEJ392X" resc1005n 3909.45,374.02 r180 bottom
R238 "ERJ-2GEJ392X" resc1005n 2712.6,188.98 r270 top
R239 "ERJ-2GEJ392X" resc1005n 1232.28,421.26 r0 bottom
R240 "HVC1206T5005JET" RESC3216N 5003.94,-39.37 r270 bottom
R241 "HVC1206T5005JET" RESC3216N 4688.98,-39.37 r270 bottom
R242 "HVC1206T5005JET" RESC3216N 4100.39,0 r0 bottom
R243 "ERJ-1GNF-1002C" RESC0603 1639.76,96.46 r270 top
RT1 "NTCG063UH103HTBX" RESC0603 1887.8,82.68 r270 top
RT2 "NTCG063UH103HTBX" RESC0603 3338.58,37.4 r90 bottom
TP1 "1V2A" testpoint 492.13,-429.13 r180 top
TP2 "1V2B" testpoint 2350.39,-311.02 r180 top
TP3 "1V2C" testpoint 2893.7,492.13 r180 top
TP4 "1V2D" testpoint 4051.18,-417.32 r180 top
TP5 "LV_RB" testpoint 1448.82,-375.98 r180 top
TP6 "1V2_RB" testpoint 1393.7,421.26 r180 top
TP7 "1V5A" testpoint 3700.79,-307.09 r180 top
TP8 "1V5D" testpoint 3637.8,-417.32 r180 top
TP9 "RX" testpoint 1665.35,-98.43 r180 top
TP10 "TX" testpoint 1663.39,285.43 r270 top
TP11 "1V0A" testpoint 452.76,456.69 r270 top
TP15 "I_1V5" testpoint 3106.3,244.09 r270 top
TP16 "I_RX" testpoint 1559.06,-287.4 r270 top
TP17 "I_TX" testpoint 1559.06,94.49 r270 top

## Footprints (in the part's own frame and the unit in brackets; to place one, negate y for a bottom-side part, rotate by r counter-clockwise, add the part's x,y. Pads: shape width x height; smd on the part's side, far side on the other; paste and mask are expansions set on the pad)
BGA196C80P14X14_1200X1200X170 [mm] "BGA, 0.80mm Pitch, Square; 196 Pin, 14 Columns X 14 Rows, 12.00mm X 12.00mm X 1.70mm H"
  round 0.4 smd mask+0.051: A1(0,0) A2(0.8,0) A3(1.6,0) A4(2.4,0) A5(3.2,0) A6(4,0) A7(4.8,0) A8(5.6,0) A9(6.4,0) A10(7.2,0) A11(8,0) A12(8.8,0) A13(9.6,0) A14(10.4,0) B1(0,-0.8) B2(0.8,-0.8) B3(1.6,-0.8) B4(2.4,-0.8) B5(3.2,-0.8) B6(4,-0.8) B7(4.8,-0.8) B8(5.6,-0.8) B9(6.4,-0.8) B10(7.2,-0.8) B11(8,-0.8) B12(8.8,-0.8) B13(9.6,-0.8) B14(10.4,-0.8) C1(0,-1.6) C2(0.8,-1.6) C3(1.6,-1.6) C4(2.4,-1.6) C5(3.2,-1.6) C6(4,-1.6) C7(4.8,-1.6) C8(5.6,-1.6) C9(6.4,-1.6) C10(7.2,-1.6) C11(8,-1.6) C12(8.8,-1.6) C13(9.6,-1.6) C14(10.4,-1.6) D1(0,-2.4) D2(0.8,-2.4) D3(1.6,-2.4) D4(2.4,-2.4) D5(3.2,-2.4) D6(4,-2.4) D7(4.8,-2.4) D8(5.6,-2.4) D9(6.4,-2.4) D10(7.2,-2.4) D11(8,-2.4) D12(8.8,-2.4) D13(9.6,-2.4) D14(10.4,-2.4) E1(0,-3.2) E2(0.8,-3.2) E3(1.6,-3.2) E4(2.4,-3.2) E5(3.2,-3.2) E6(4,-3.2) E7(4.8,-3.2) E8(5.6,-3.2) E9(6.4,-3.2) E10(7.2,-3.2) E11(8,-3.2) E12(8.8,-3.2) E13(9.6,-3.2) E14(10.4,-3.2) F1(0,-4) F2(0.8,-4) F3(1.6,-4) F4(2.4,-4) F5(3.2,-4) F6(4,-4) F7(4.8,-4) F8(5.6,-4) F9(6.4,-4) F10(7.2,-4) F11(8,-4) F12(8.8,-4) F13(9.6,-4) F14(10.4,-4) G1(0,-4.8) G2(0.8,-4.8) G3(1.6,-4.8) G4(2.4,-4.8) G5(3.2,-4.8) G6(4,-4.8) G7(4.8,-4.8) G8(5.6,-4.8) G9(6.4,-4.8) G10(7.2,-4.8) G11(8,-4.8) G12(8.8,-4.8) G13(9.6,-4.8) G14(10.4,-4.8) H1(0,-5.6) H2(0.8,-5.6) H3(1.6,-5.6) H4(2.4,-5.6) H5(3.2,-5.6) H6(4,-5.6) H7(4.8,-5.6) H8(5.6,-5.6) H9(6.4,-5.6) H10(7.2,-5.6) H11(8,-5.6) H12(8.8,-5.6) H13(9.6,-5.6) H14(10.4,-5.6) J1(0,-6.4) J2(0.8,-6.4) J3(1.6,-6.4) J4(2.4,-6.4) J5(3.2,-6.4) J6(4,-6.4) J7(4.8,-6.4) J8(5.6,-6.4) J9(6.4,-6.4) J10(7.2,-6.4) J11(8,-6.4) J12(8.8,-6.4) J13(9.6,-6.4) J14(10.4,-6.4) K1(0,-7.2) K2(0.8,-7.2) K3(1.6,-7.2) K4(2.4,-7.2) K5(3.2,-7.2) K6(4,-7.2) K7(4.8,-7.2) K8(5.6,-7.2) K9(6.4,-7.2) K10(7.2,-7.2) K11(8,-7.2) K12(8.8,-7.2) K13(9.6,-7.2) K14(10.4,-7.2) L1(0,-8) L2(0.8,-8) L3(1.6,-8) L4(2.4,-8) L5(3.2,-8) L6(4,-8) L7(4.8,-8) L8(5.6,-8) L9(6.4,-8) L10(7.2,-8) L11(8,-8) L12(8.8,-8) L13(9.6,-8) L14(10.4,-8) M1(0,-8.8) M2(0.8,-8.8) M3(1.6,-8.8) M4(2.4,-8.8) M5(3.2,-8.8) M6(4,-8.8) M7(4.8,-8.8) M8(5.6,-8.8) M9(6.4,-8.8) M10(7.2,-8.8) M11(8,-8.8) M12(8.8,-8.8) M13(9.6,-8.8) M14(10.4,-8.8) N1(0,-9.6) N2(0.8,-9.6) N3(1.6,-9.6) N4(2.4,-9.6) N5(3.2,-9.6) N6(4,-9.6) N7(4.8,-9.6) N8(5.6,-9.6) N9(6.4,-9.6) N10(7.2,-9.6) N11(8,-9.6) N12(8.8,-9.6) N13(9.6,-9.6) N14(10.4,-9.6) P1(0,-10.4) P2(0.8,-10.4) P3(1.6,-10.4) P4(2.4,-10.4) P5(3.2,-10.4) P6(4,-10.4) P7(4.8,-10.4) P8(5.6,-10.4) P9(6.4,-10.4) P10(7.2,-10.4) P11(8,-10.4) P12(8.8,-10.4) P13(9.6,-10.4) P14(10.4,-10.4)
  silkscreen extent -0.8,-11.2 11.2,0.8, body extent -0.8,-11.2 11.2,0.8, height 1.7
BGA289X17 [mm]
  round 0.27 smd: A1(0,0) A2(0.5,0) A3(1,0) A4(1.5,0) A5(2,0) A6(2.5,0) A7(3,0) A8(3.5,0) A9(4,0) A10(4.5,0) A11(5,0) A12(5.5,0) A13(6,0) A14(6.5,0) A15(7,0) A16(7.5,0) A17(8,0) B1(0,-0.5) B2(0.5,-0.5) B3(1,-0.5) B4(1.5,-0.5) B5(2,-0.5) B6(2.5,-0.5) B7(3,-0.5) B8(3.5,-0.5) B9(4,-0.5) B10(4.5,-0.5) B11(5,-0.5) B12(5.5,-0.5) B13(6,-0.5) B14(6.5,-0.5) B15(7,-0.5) B16(7.5,-0.5) B17(8,-0.5) C1(0,-1) C2(0.5,-1) C3(1,-1) C4(1.5,-1) C5(2,-1) C6(2.5,-1) C7(3,-1) C8(3.5,-1) C9(4,-1) C10(4.5,-1) C11(5,-1) C12(5.5,-1) C13(6,-1) C14(6.5,-1) C15(7,-1) C16(7.5,-1) C17(8,-1) D1(0,-1.5) D2(0.5,-1.5) D3(1,-1.5) D4(1.5,-1.5) D5(2,-1.5) D6(2.5,-1.5) D7(3,-1.5) D8(3.5,-1.5) D9(4,-1.5) D10(4.5,-1.5) D11(5,-1.5) D12(5.5,-1.5) D13(6,-1.5) D14(6.5,-1.5) D15(7,-1.5) D16(7.5,-1.5) D17(8,-1.5) E1(0,-2) E2(0.5,-2) E3(1,-2) E4(1.5,-2) E5(2,-2) E6(2.5,-2) E7(3,-2) E8(3.5,-2) E9(4,-2) E10(4.5,-2) E11(5,-2) E12(5.5,-2) E13(6,-2) E14(6.5,-2) E15(7,-2) E16(7.5,-2) E17(8,-2) F1(0,-2.5) F2(0.5,-2.5) F3(1,-2.5) F4(1.5,-2.5) F5(2,-2.5) F6(2.5,-2.5) F7(3,-2.5) F8(3.5,-2.5) F9(4,-2.5) F10(4.5,-2.5) F11(5,-2.5) F12(5.5,-2.5) F13(6,-2.5) F14(6.5,-2.5) F15(7,-2.5) F16(7.5,-2.5) F17(8,-2.5) G1(0,-3) G2(0.5,-3) G3(1,-3) G4(1.5,-3) G5(2,-3) G6(2.5,-3) G7(3,-3) G8(3.5,-3) G9(4,-3) G10(4.5,-3) G11(5,-3) G12(5.5,-3) G13(6,-3) G14(6.5,-3) G15(7,-3) G16(7.5,-3) G17(8,-3) H1(0,-3.5) H2(0.5,-3.5) H3(1,-3.5) H4(1.5,-3.5) H5(2,-3.5) H6(2.5,-3.5) H7(3,-3.5) H8(3.5,-3.5) H9(4,-3.5) H10(4.5,-3.5) H11(5,-3.5) H12(5.5,-3.5) H13(6,-3.5) H14(6.5,-3.5) H15(7,-3.5) H16(7.5,-3.5) H17(8,-3.5) J1(0,-4) J2(0.5,-4) J3(1,-4) J4(1.5,-4) J5(2,-4) J6(2.5,-4) J7(3,-4) J8(3.5,-4) J9(4,-4) J10(4.5,-4) J11(5,-4) J12(5.5,-4) J13(6,-4) J14(6.5,-4) J15(7,-4) J16(7.5,-4) J17(8,-4) K1(0,-4.5) K2(0.5,-4.5) K3(1,-4.5) K4(1.5,-4.5) K5(2,-4.5) K6(2.5,-4.5) K7(3,-4.5) K8(3.5,-4.5) K9(4,-4.5) K10(4.5,-4.5) K11(5,-4.5) K12(5.5,-4.5) K13(6,-4.5) K14(6.5,-4.5) K15(7,-4.5) K16(7.5,-4.5) K17(8,-4.5) L1(0,-5) L2(0.5,-5) L3(1,-5) L4(1.5,-5) L5(2,-5) L6(2.5,-5) L7(3,-5) L8(3.5,-5) L9(4,-5) L10(4.5,-5) L11(5,-5) L12(5.5,-5) L13(6,-5) L14(6.5,-5) L15(7,-5) L16(7.5,-5) L17(8,-5) M1(0,-5.5) M2(0.5,-5.5) M3(1,-5.5) M4(1.5,-5.5) M5(2,-5.5) M6(2.5,-5.5) M7(3,-5.5) M8(3.5,-5.5) M9(4,-5.5) M10(4.5,-5.5) M11(5,-5.5) M12(5.5,-5.5) M13(6,-5.5) M14(6.5,-5.5) M15(7,-5.5) M16(7.5,-5.5) M17(8,-5.5) N1(0,-6) N2(0.5,-6) N3(1,-6) N4(1.5,-6) N5(2,-6) N6(2.5,-6) N7(3,-6) N8(3.5,-6) N9(4,-6) N10(4.5,-6) N11(5,-6) N12(5.5,-6) N13(6,-6) N14(6.5,-6) N15(7,-6) N16(7.5,-6) N17(8,-6) P1(0,-6.5) P2(0.5,-6.5) P3(1,-6.5) P4(1.5,-6.5) P5(2,-6.5) P6(2.5,-6.5) P7(3,-6.5) P8(3.5,-6.5) P9(4,-6.5) P10(4.5,-6.5) P11(5,-6.5) P12(5.5,-6.5) P13(6,-6.5) P14(6.5,-6.5) P15(7,-6.5) P16(7.5,-6.5) P17(8,-6.5) R1(0,-7) R2(0.5,-7) R3(1,-7) R4(1.5,-7) R5(2,-7) R6(2.5,-7) R7(3,-7) R8(3.5,-7) R9(4,-7) R10(4.5,-7) R11(5,-7) R12(5.5,-7) R13(6,-7) R14(6.5,-7) R15(7,-7) R16(7.5,-7) R17(8,-7) T1(0,-7.5) T2(0.5,-7.5) T3(1,-7.5) T4(1.5,-7.5) T5(2,-7.5) T6(2.5,-7.5) T7(3,-7.5) T8(3.5,-7.5) T9(4,-7.5) T10(4.5,-7.5) T11(5,-7.5) T12(5.5,-7.5) T13(6,-7.5) T14(6.5,-7.5) T15(7,-7.5) T16(7.5,-7.5) T17(8,-7.5) U1(0,-8) U2(0.5,-8) U3(1,-8) U4(1.5,-8) U5(2,-8) U6(2.5,-8) U7(3,-8) U8(3.5,-8) U9(4,-8) U10(4.5,-8) U11(5,-8) U12(5.5,-8) U13(6,-8) U14(6.5,-8) U15(7,-8) U16(7.5,-8) U17(8,-8)
  silkscreen extent -0.5,-8.5 8.5,0.5, body extent -0.5,-8.5 8.5,0.5, height 1.3
CAPC0603N [mm] "Chip Capacitor, 2-Leads, Body 0.60x0.30mm, IPC Medium Density"
  rect 0.52x0.42 smd: 1(-0.31,0) 2(0.31,0)
  body extent -0.32,-0.17 0.32,0.17, height 0.3
capc1005n [mm] "Chip Capacitor, Body 1.0x0.5mm, IPC Medium Density"
  rect 0.8x0.6 smd: 1(-0.6,0) 2(0.6,0)
  silkscreen extent -1.3,-0.2 -1.3,0.2, body extent -0.55,-0.3 0.55,0.3, height 0.6
CAPC1005N [mm] "Chip Capacitor, Body 1.0x0.5mm, IPC Medium Density"
  rect 0.8x0.6 smd: 1(-0.6,0) 2(0.6,0)
  silkscreen extent -1.3,-0.2 -1.3,0.2, body extent -0.55,-0.3 0.55,0.3, height 0.6
CAPC1608N [mm] "Chip Capacitor, Body 1.6x0.8mm, IPC Medium Density"
  rect 1x1 smd: 1(-0.8,0) 2(0.8,0)
  silkscreen extent -1.6,-0.4 -1.6,0.4, body extent -0.87,-0.48 0.87,0.48, height 0.55
capc2012n [mm] "Chip Capacitor, Body 2.0x1.3mm, IPC Medium Density"
  rect 1.3x1.5 smd: 1(-0.85,0) 2(0.85,0)
  silkscreen extent -1.8,-0.65 -1.8,0.65, body extent -1.1,-0.72 1.1,0.72, height 1.1
cnc10 [mm]
  rect 1.2x4.75 smd: 1(0,0) 2(0,5.75) 3(2.54,0) 4(2.54,5.75) 5(5.08,0) 6(5.08,5.75) 7(7.62,0) 8(7.62,5.75) 9(10.16,0) 10(10.16,5.75)
  silkscreen extent -5.1,-3.88 15.24,8.2, body extent -5.08,-2.54 15.24,8.2, height 10
cnc14 [mm]
  rect 1.2x4.75 smd: 1(0,0) 2(0,5.75) 3(2.54,0) 4(2.54,5.75) 5(5.08,0) 6(5.08,5.75) 7(7.62,0) 8(7.62,5.75) 9(10.16,0) 10(10.16,5.75) 11(12.7,0) 12(12.7,5.75) 13(15.24,0) 14(15.24,5.75)
  silkscreen extent -5.1,-3.88 20.3,8.2, body extent -5.08,-2.54 20.32,8.2, height 10
CONTACT [mm]
  rect 1.85x0.9 smd: 1(0,0)
  silkscreen extent -2,-0.6 1.2,0.6, body extent -1.92,-0.5 1.34,0.5, height 1.24
DF57-2 [mm]
  rect 0.6x0.85 smd: 1(0,0) 2(1.2,0)
  rect 0.7x0.8 smd: 3(2.35,3.775) 4(-1.15,3.775)
  silkscreen extent -1.5,-0.4 2.7,3, body extent -1.5,0 2.7,3.8, height 1.6
DF57-3 [mm]
  rect 0.6x0.85 smd: 1(0,0) 2(1.2,0) 3(2.4,0)
  rect 0.7x0.8 smd: 4(3.55,3.775) 5(-1.15,3.775)
  silkscreen extent -1.5,-0.4 3.9,3, body extent -1.5,-0.25 3.9,4, height 1.6
JMP2PCB#1 [mm]
  round 0.2 smd paste-1 mask-1: 1(0,-0.5) 2(0,0.45)
  oval 1.4x1.8 on Bottom Solder paste-1 mask-1: 9(0,0)
  Top Layer lines w0.254: -0.25,-0.45 -0.166,-0.45 ; 0.25,-0.45 0.166,-0.45 ; -0.3,0.2 cw(c0,0.2) 0.3,0.2 ; -0.25,0.45 0.25,0.45 ; -0.166,-0.45 ccw(c0,-0.2) 0,-0.5 ccw(c0,-0.2) 0.166,-0.45 ; -0.166,-0.45 cw(c0,-0.2) -0.3,-0.2 ; -0.166,-0.45 0,-0.45 0.166,-0.45 ; 0.166,-0.45 ccw(c0,-0.2) 0.3,-0.2 ; -0.3,-0.2 0.3,-0.2 ; -0.3,-0.2 -0.5,-0.2 ccw(c0,-0.2) -0.433,-0.45 ccw(c0,-0.2) 0.05,-0.697 ccw(c0,-0.2) 0.477,-0.35 ccw(c0,-0.2) 0.5,-0.2 0.3,-0.2 ; -0.5,0.2 cw(c0,0.2) 0.5,0.2 -0.5,0.2
JMP2PCB#2 [mm]
  round 0.2 smd paste-1 mask-1: 1(0,-0.5) 2(0,0.45)
  oval 1.4x1.8 on Bottom Solder paste-1 mask-1: 9(0,0)
  Top Layer lines w0.254: -0.25,-0.45 -0.166,-0.45 ; 0.25,-0.45 0.166,-0.45 ; -0.3,0.2 cw(c0,0.2) -0.166,0.45 ; 0.3,0.2 ccw(c0,0.2) 0.166,0.45 ; -0.25,0.45 -0.166,0.45 ; 0.25,0.45 0.166,0.45 ; -0.166,-0.45 ccw(c0,-0.2) 0,-0.5 ccw(c0,-0.2) 0.166,-0.45 ; -0.166,-0.45 cw(c0,-0.2) -0.3,-0.2 ; -0.166,-0.45 0,-0.45 0.166,-0.45 ; 0.166,-0.45 ccw(c0,-0.2) 0.3,-0.2 ; -0.3,-0.2 -0.5,-0.2 ccw(c0,-0.2) -0.433,-0.45 ccw(c0,-0.2) 0.05,-0.697 ccw(c0,-0.2) 0.5,-0.2 0.3,-0.2 ; -0.3,-0.2 0.3,-0.2 ; -0.166,0.45 cw(c0,0.2) 0.166,0.45 ; -0.166,0.45 0,0.45 0.166,0.45 ; -0.5,0.2 cw(c0,0.2) 0.166,0.672 cw(c0,0.2) 0.5,0.2 -0.5,0.2
LED_RED [mm] "LTST-C194KRKT"
  rect 0.8x0.8 smd: 1(0,0) 2(1.5,0)
  body extent -0.1,-0.45 1.6,0.45, height 0.6
RESC0603 [mm]
  rect 0.35x0.4 smd: 1(0,0) 2(0.65,0)
  body extent 0,-0.15 0.65,0.15, height 0.5
resc0603 [mm]
  rect 0.35x0.4 smd: 1(0,0) 2(0.65,0)
  body extent 0,-0.15 0.65,0.15, height 0.5
resc1005n [mm] "Chip Resistor, Body 1.1x0.5mm, IPC Medium Density"
  rect 0.8x0.7 smd: 1(-0.6,0) 2(0.6,0)
  body extent -0.55,-0.3 0.55,0.3, height 0.4
RESC3216N [mm] "Chip Resistor, Body 3.2x1.6mm, IPC Medium Density"
  rect 1.3x1.8 smd: 1(-1.45,0) 2(1.45,0)
  silkscreen extent -0.4,-0.8 0.4,0.8, body extent -1.68,-0.87 1.68,0.87, height 0.55
SOT-23 [mm]
  rect 0.6x1.25 smd: 1(0,0) 2(1.9,0) 3(0.95,2)
  silkscreen extent 0,0 1.9,2, body extent 0,0.3 1.9,1.7, height 1.2
testpoint [mil]
  round 40 smd paste-39.37: 1(0,0)
  silkscreen extent -39,-39 39,39
VENKEL0805 [mm]
  rect 1.1x1.2 smd: 1(0,0) 2(1.9,0)
  body extent -0.75,-0.8 2.65,0.8, height 1.7
VTRX+ [mm]
  rect 0.2x1.12 smd: 1(0,0) 2(0,2.66) 3(0.4,0) 4(0.4,2.66) 5(0.8,0) 6(0.8,2.66) 7(1.2,0) 8(1.2,2.66) 9(1.6,0) 10(1.6,2.66) 11(2,0) 12(2,2.66) 13(2.4,0) 14(2.4,2.66) 15(2.8,0) 16(2.8,2.66) 17(3.2,0) 18(3.2,2.66) 19(3.6,0) 20(3.6,2.66) 21(4,0) 22(4,2.66) 23(4.4,0) 24(4.4,2.66) 25(4.8,0) 26(4.8,2.66) 27(5.2,0) 28(5.2,2.66) 29(5.6,0) 30(5.6,2.66) 31(6,0) 32(6,2.66) 33(6.4,0) 34(6.4,2.66) 35(6.8,0) 36(6.8,2.66) 37(7.2,0) 38(7.2,2.66) 39(7.6,0) 40(7.6,2.66)
  silkscreen extent -1.2,-2.6 8.8,17.4, body extent -1.2,-2.6 8.8,17.4, height 2
WDFNX208 [mm]
  rect 0.3x0.5 smd: 1(0,0) 2(0.5,0) 3(1,0) 4(1.5,0) 5(1.5,1.8) 6(1,1.8) 7(0.5,1.8) 8(0,1.8)
  rect 1.6x0.9 smd: 9(0.75,0.9)
  silkscreen extent -0.57,-0.07 1.73,1.35, body extent -0.25,-0.12 1.75,1.87, height 0.8
WP7B-40P [mm]
  rect 0.22x0.55 smd: 1(0,0) 2(0.4,0) 3(0.8,0) 4(1.2,0) 5(1.6,0) 6(2,0) 7(2.4,0) 8(2.8,0) 9(3.2,0) 10(3.6,0) 11(4,0) 12(4.4,0) 13(4.8,0) 14(5.2,0) 15(5.6,0) 16(6,0) 17(6.4,0) 18(6.8,0) 19(7.2,0) 20(7.6,0) 21(7.6,1.85) 22(7.2,1.85) 23(6.8,1.85) 24(6.4,1.85) 25(6,1.85) 26(5.6,1.85) 27(5.2,1.85) 28(4.8,1.85) 29(4.4,1.85) 30(4,1.85) 31(3.6,1.85) 32(3.2,1.85) 33(2.8,1.85) 34(2.4,1.85) 35(2,1.85) 36(1.6,1.85) 37(1.2,1.85) 38(0.8,1.85) 39(0.4,1.85) 40(0,1.85) 41(-0.4,0) 42(8,0) 43(8,1.85) 44(-0.4,1.85)
  silkscreen extent -0.65,-1 8.25,2.3, body extent -1.5,-0.32 9.1,2.17, height 0.5

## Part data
C105 C106 C107 C108 C109 C111 C112 C113 C114 C115 C116 C117 C118 C119 C120 C121 C122 C123 C124 C125 C126 C127 C128 C129 C130 C131 C132 C133 C134 C135 C136 C138 C139 C140 C141 C150 C151 C152 C153 C154 C155 C160 C162 C163 C164 C165 C166 C167 C168 C169 C201 C202 C203 C204 C205 C206 C207 C208 C209 C210 C211 C212 C213 C214 C215 C216 C217 C218 C219 C220 C221 C222 C223 C224 C225 C226 C227 C228 C229 C230 C231 C232 C233: library part C, "CERAMIC CAPACITOR"
CT1 CT2 CT3: library part CONTACT
D1: library part LED2, "Typical RED, GREEN, YELLOW, AMBER GaAs LED"
IC1 IC4: "Low Power Gigabit Transceiver", Case=BGA289, Manufacturer=CERN
IC2: library part VTRX+_DF40C-2.0-40DS-0.4V, "VTRX+ module with 2.5mm stack Height."
IC3: library part "CERN_GBT-SCA_REV 6.2", "The Slow Control Adapter ASIC for the GBT System"
JMP1 JMP2: library part JMP2, "printed on PCB"
P1: library part "Header 5X2", "Header, 5-Pin, Dual row"
P2 P3 P11 P14 P15: library part "Header 7X2", "Header, 7-Pin, Dual row"
P4 P16 P17: library part "Header 4", "Header, 4-Pin"
P5 P6 P7 P8 P9 P10: library part WP7B-40P, "plug"
P12: library part "Header 5", "Header, 5-Pin"
Q1: library part NPN, "NPN Bipolar Transistor"
R101 R102 R103 R104 R105 R106 R107 R109 R110 R111 R112 R113 R114 R115 R116 R117 R118 R119 R120 R122 R123 R124 R125 R126 R127 R128 R129 R130 R131 R132 R133 R134 R135 R141 R142 R143 R144 R145 R146 R147 R148 R201 R202 R203 R204 R205 R206 R207 R208 R209 R210 R211 R213 R214 R215 R216 R217 R218 R219 R220 R221 R222 R223 R224 R225 R226 R227 R228 R229 R230 R231 R232 R233 R234 R235 R236 R237 R238 R239 R240 R241 R242 R243: library part R1, "FILM RESISTOR"
RT1 RT2: library part "Res Thermal", "Thermistor"
TP1 TP2 TP3 TP4 TP5 TP6 TP7 TP8 TP9 TP10 TP11 TP15 TP16 TP17: library part TP, "TEST POINT 40MIL DIA."

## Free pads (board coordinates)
  round 15.75 hole 9.84 mask+2: 1(442.91,0) 1(1011.81,141.73) 1(1015.75,-330.71) 1(1051.18,-267.72) 1(1080.71,23.62) 1(1080.71,70.87) 1(1082.68,-118.11) 1(1082.68,-70.87) 1(1086.61,-39.37) 1(1086.61,-13.78) 1(1086.61,110.24) 1(1102.36,-55.12) 1(1118.11,-283.46) 1(1118.11,-149.61) 1(1118.11,-118.11) 1(1118.11,-70.87) 1(1122.05,-23.62) 1(1122.05,23.62) 1(1122.05,70.87) 1(1122.05,118.11) 1(1141.73,-330.71) 1(2436.02,-231.3) 1(2475.39,-231.3) 1(2582.68,35.43) 1(2700.79,118.11) 1(2712.6,271.65) 1(2720.47,98.43) 1(2740.16,-70.87) 1(2755.91,-147.64) 1(3350.39,-96.46) 1(3352.36,-33.46) 1(3795.27,-125.98) 1(3795.28,-188.98) 1(3795.28,-157.48) 1(3795.28,-94.49) 1(3795.28,-62.99) 1(3795.28,-31.5) 1(3795.28,31.5) 1(3795.28,62.99) 1(4154.77,219.24) 1(4338.58,-51.18) 1(4488.19,255.91) 1(4641.73,-94.49) 1(4688.98,362.2) 1(4688.98,251.97) 1(4956.69,-94.49) 1(5003.94,362.2) 1(5003.94,248.03)
  round 9.84 / inner round 13.78 / far side round 13.78 hole 5.91 mask+2: 1(2021.65,114.17) 1(2037.4,68.9) 1(2037.4,-9.84) 1(2057.09,-68.9) 1(2057.09,-49.21) 1(2057.09,-29.53) 1(2057.09,9.84) 1(2057.09,29.53) 1(2057.09,49.21) 1(2057.09,-9.84) 1(2076.77,-68.9) 1(2076.77,-29.53) 1(2076.77,-49.21) 1(2076.77,-9.84) 1(2076.77,49.21) 1(2076.77,88.58) 1(2076.77,127.95) 1(2096.46,9.84) 1(2096.46,49.21) 1(2096.46,-29.53) 1(2096.46,-9.84) 1(2096.46,29.53) 1(2096.46,127.95) 1(2096.46,-68.9) 1(2096.46,-49.21) 1(2096.46,88.58) 1(2096.46,-127.95) 1(2096.46,-108.27) 1(2106.3,-173.23) 1(2116.14,-147.64) 1(2116.14,29.53) 1(2116.14,49.21) 1(2116.14,-108.27) 1(2116.14,88.58) 1(2116.14,108.27) 1(2135.83,-127.95) 1(2135.83,-108.27) 1(2135.83,-9.84) 1(2135.83,-68.9) 1(2135.83,-29.53) 1(2135.83,127.95) 1(2135.83,9.84) 1(2135.86,48.28) 1(2136.79,88.58) 1(2155.51,9.84) 1(2155.51,29.53) 1(2155.51,49.21) 1(2155.51,-29.53) 1(2155.51,-9.84) 1(2156.48,88.58) 1(2175.2,-127.95) 1(2175.2,-108.27) 1(2175.2,-29.53) 1(2175.2,9.84) 1(2175.2,29.53) 1(2175.2,49.21) 1(2175.2,-68.9) 1(2175.2,-9.84) 1(2175.2,-49.21) 1(2194.88,108.27) 1(2194.88,127.95) 1(2194.88,-147.64) 1(2194.88,-29.53) 1(2194.88,9.84) 1(2194.88,29.53) 1(2194.88,49.21) 1(2194.88,-9.84) 1(2194.88,-167.32) 1(2194.88,-108.27) 1(2214.57,-9.84) 1(2214.57,-68.9) 1(2214.57,-49.21) 1(2214.57,108.27) 1(2214.57,-127.95) 1(2214.57,-108.27) 1(2224.41,-173.23) 1(2234.25,108.27) 1(2234.25,127.95) 1(2234.25,-9.84) 1(2234.25,-147.64) 1(2234.25,29.53) 1(2234.25,49.21) 1(2234.25,-49.21) 1(2253.94,29.53) 1(2253.94,49.21) 1(2253.94,-9.84) 1(2253.94,-108.27) 1(2253.94,-29.53) 1(2253.94,108.27) 1(2273.62,108.27) 1(2273.62,127.95) 1(2273.62,-127.95) 1(2273.62,-108.27) 1(2273.62,-9.84) 1(2273.62,29.53) 1(2273.62,49.21) 1(2273.62,-68.9) 1(2273.62,-49.21) 1(2273.62,-29.53) 1(2293.31,9.84) 1(2293.31,29.53) 1(2293.31,49.21) 1(2293.31,-29.53) 1(2293.31,-49.21) 1(2293.31,-68.9) 1(2293.31,-9.84) 1(2293.31,108.27) 1(2293.31,127.95) 1(2312.99,-127.95) 1(2312.99,-108.27) 1(2312.99,-68.9) 1(2312.99,108.27) 1(2312.99,127.95) 1(2312.99,147.64) 1(2313.07,167.32) 1(2332.58,-148.45) 1(2332.59,127.48) 1(2332.68,108.27) 1(2332.68,-127.95) 1(2332.68,-68.9) 1(2332.68,-49.21) 1(2332.68,-29.53) 1(2332.68,-9.84) 1(2332.68,9.84) 1(2332.68,147.64) 1(2332.68,167.32) 1(2352.36,-147.64) 1(2352.36,-127.95) 1(2352.36,127.95) 1(2352.36,167.32) 1(2352.36,-167.32) 1(2352.36,-68.9) 1(2352.36,-9.84) 1(2352.36,147.64) 1(2372.05,-127.95) 1(2372.05,167.32) 1(2372.05,127.95) 1(2779.53,19.68) 1(2779.53,39.37) 1(2785.43,-68.9) 1(2785.43,-29.53) 1(2785.43,-9.84) 1(2785.43,68.9) 1(2805.12,-147.64) 1(2805.12,-127.95) 1(2805.12,-108.27) 1(2805.12,29.53) 1(2805.12,-68.9) 1(2805.12,-29.53) 1(2805.12,-9.84) 1(2805.12,49.21) 1(2805.12,68.9) 1(2824.8,-9.84) 1(2824.8,-147.64) 1(2824.8,-108.27) 1(2824.8,49.21) 1(2824.8,68.9) 1(2824.8,-127.95) 1(2824.8,-68.9) 1(2824.8,-29.53) 1(2844.49,-9.84) 1(2844.49,-108.27) 1(2844.49,-68.9) 1(2844.49,-49.21) 1(2844.49,-29.53) 1(2844.49,29.53) 1(2844.49,88.58) 1(2864.17,-127.95) 1(2864.17,88.58) 1(2864.17,49.21) 1(2864.17,68.9) 1(2864.17,-147.64) 1(2883.86,-167.32) 1(2883.86,-9.84) 1(2883.86,-147.64) 1(2883.86,-29.53) 1(2883.86,9.84) 1(2883.86,29.53) 1(2903.54,-29.53) 1(2903.54,-9.84) 1(2903.54,-127.95) 1(2903.54,9.84) 1(2903.54,29.53) 1(2903.54,49.21) 1(2903.54,-147.64) 1(2923.23,-167.32) 1(2923.23,-9.84) 1(2923.23,49.21) 1(2923.23,147.64) 1(2923.23,167.32) 1(2923.23,-29.53) 1(2923.44,-147.82) 1(2942.91,-9.84) 1(2942.91,9.84) 1(2942.91,29.53) 1(2942.91,49.21) 1(2942.91,147.64) 1(2942.91,-88.58) 1(2942.91,-29.53) 1(2942.91,127.95) 1(2962.6,-29.53) 1(2962.6,29.53) 1(2962.6,49.21) 1(2962.6,167.32) 1(2962.6,-49.21) 1(2962.6,9.84) 1(2962.6,147.64) 1(2982.28,29.53) 1(2982.28,49.21) 1(2982.28,147.64) 1(2982.28,-127.95) 1(2982.28,-108.27) 1(2982.28,-49.21) 1(2982.28,-29.53) 1(2982.28,127.95) 1(2982.28,-147.64) 1(3001.97,-167.32) 1(3001.97,9.84) 1(3001.97,29.53) 1(3001.97,49.21) 1(3001.97,167.32) 1(3001.97,-147.64) 1(3001.97,147.64) 1(3021.65,9.84) 1(3021.65,29.53) 1(3021.65,49.21) 1(3021.65,147.64) 1(3021.65,-147.64) 1(3021.65,-127.95) 1(3021.65,-108.27) 1(3021.65,-49.21) 1(3021.65,-29.53) 1(3021.65,-9.84) 1(3021.65,127.95) 1(3041.34,-167.32) 1(3041.34,9.84) 1(3041.34,29.53) 1(3041.34,167.32) 1(3041.34,-147.64) 1(3041.34,-49.21) 1(3041.34,-29.53) 1(3041.34,-9.84) 1(3041.34,49.21) 1(3041.34,147.64) 1(3061.02,147.64) 1(3061.02,-108.27) 1(3061.02,68.9) 1(3061.02,127.95) 1(3080.71,-88.58) 1(3080.71,-68.9) 1(3080.71,29.53) 1(3080.71,49.21) 1(3080.71,68.9) 1(3080.71,-108.27) 1(3100.39,-68.9) 1(3100.39,-88.58) 1(3100.39,-49.21) 1(3100.39,9.84) 1(3100.39,29.53) 1(3100.39,49.21) 1(3100.39,68.9) 1(3100.39,-108.27) 1(3120.08,-49.21) 1(3120.08,9.84)
  round 18.9 hole 11.81 mask+2: 1(3354.33,-62.99) 1(3354.33,125.98) 1(3385.83,94.49) 1(3385.83,31.5) 1(3417.32,31.5) 1(3417.32,94.49) 1(3448.82,-125.98) 1(3448.82,-94.49) 1(3448.82,-62.99) 1(3448.82,-31.5) 1(3448.82,0) 1(3448.82,31.5) 1(3448.82,-157.48) 1(3448.82,125.98) 1(3480.31,31.5) 1(3480.31,62.99) 1(3480.31,94.49) 1(3480.31,-31.5) 1(3480.31,0) 1(3480.32,-94.49) 1(3480.32,-62.99) 1(3480.32,-188.98) 1(3480.32,-157.48) 1(3511.8,-188.98) 1(3511.81,-157.48) 1(3511.81,-125.98) 1(3511.81,62.99) 1(3511.81,94.49) 1(3511.81,-220.47) 1(3511.81,-94.49) 1(3511.81,-62.99) 1(3511.81,-31.5) 1(3511.81,0) 1(3511.81,31.5) 1(3543.3,-188.98) 1(3543.31,0) 1(3543.31,31.5) 1(3543.31,-157.48) 1(3543.31,62.99) 1(3543.31,94.49) 1(3543.31,-220.47) 1(3574.8,-94.49) 1(3574.8,-220.47) 1(3574.8,-188.98) 1(3574.8,-157.48) 1(3574.8,-125.98) 1(3574.8,94.49) 1(3574.8,-62.99) 1(3574.8,-31.5) 1(3606.3,-94.49) 1(3606.3,-220.47) 1(3606.3,-188.98) 1(3606.3,-157.48) 1(3606.3,-125.98) 1(3606.3,-62.99) 1(3606.3,62.99) 1(3606.3,94.49) 1(3606.3,0) 1(3606.3,31.5) 1(3637.8,31.5) 1(3637.8,62.99) 1(3637.8,94.49) 1(3637.8,125.98) 1(3637.8,-94.49) 1(3637.8,-62.99) 1(3637.8,-31.5) 1(3637.8,0) 1(3669.29,-125.98) 1(3669.29,-94.49) 1(3669.29,-62.99) 1(3669.29,0) 1(3669.29,31.5) 1(3669.29,62.99) 1(3669.29,94.49) 1(3669.29,125.98) 1(3700.79,-125.98) 1(3700.79,0) 1(3700.79,31.5) 1(3700.79,62.99) 1(3700.79,94.49) 1(3700.79,125.98) 1(3700.79,-62.99) 1(3700.79,-31.5)

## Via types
v1: diameter 15.75, hole 9.84, Top Layer to Bottom Layer, 978 vias

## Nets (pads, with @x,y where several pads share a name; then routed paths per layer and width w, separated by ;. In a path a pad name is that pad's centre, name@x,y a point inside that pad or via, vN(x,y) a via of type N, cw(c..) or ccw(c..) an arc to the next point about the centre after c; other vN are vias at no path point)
1V0A: P5.20 P7.20 P9.20 R201.1 TP11.1 | length 6906.1
  Top Layer w4: TP11.1@452.76,456.69 566.93,342.52 v1(700.79,342.52) ; v1(1702.76,82.68) R201.1@1738.19,82.68
  M1 w4: v1(700.79,342.52) 803.15,240.16 1330.71,240.16 1488.19,82.68 v1(1702.76,82.68) ; v1(2279.53,613.11) 2279.53,614.17 4452.76,614.17 4476.38,590.55 4476.38,562.99 4409.45,496.06 4244.09,496.06 v1(4153.54,405.51)
  Bottom Layer w4: P5.20@716.54,472.44 716.54,358.27 v1(700.79,342.52) 594.49,342.52 566.93,370.08 566.93,531.5 728.35,692.91 2200.79,692.91 2279.53,614.17 2279.53,377.95 2307.09,350.39 2425.2,350.39 2433.07,358.27 P7.20@2433.07,472.44 ; P9.20@4149.61,472.44 4149.61,409.45 v1(4153.54,405.51)
1V2_mon0: C201.2 IC3.P14 P5.17 pad.1@2755.91,-147.64 R203.2 | length 3325.5
  Top Layer w4: C201.2@3259.84,-220.47 v1(3295.28,-220.47) 3354.33,-220.47 IC3.P14@3370.08,-204.72
  M2 w4: pad.1@2755.91,-147.64 2809.06,-200.79 3275.59,-200.79 v1(3295.28,-220.47)
  Bottom Layer w4: P5.17@763.78,472.44 763.78,358.27 783.46,338.58 1370.08,338.58 1417.32,385.83 1944.88,385.83 2110.24,220.47 2433.07,220.47 2476.38,177.17 2696.85,177.17 2755.91,118.11 pad.1@2755.91,-147.64 ; R203.2@3259.84,-322.83 3279.53,-322.83 3295.28,-307.09 v1(3295.28,-220.47)
1V2_mon1: C202.2 IC3.P13 P5.18 pad.1@2740.16,-70.87 R205.2 | length 3241.6
  Top Layer w4: v1(3295.28,-196.85) 3346.46,-196.85 IC3.P13@3370.08,-173.23
  M2 w4: pad.1@2740.16,-70.87 2785.43,-116.14 2785.43,-147.64 2824.8,-187.01 3285.43,-187.01 v1(3295.28,-196.85)
  Bottom Layer w4: P5.18@748.03,472.44 748.03,354.33 779.53,322.83 1377.95,322.83 1429.13,374.02 1933.07,374.02 2098.43,208.66 2413.39,208.66 2456.69,165.35 2685.04,165.35 2740.16,110.24 pad.1@2740.16,-70.87 ; R205.2@3259.84,-271.65 C202.2@3259.84,-220.47 3271.65,-220.47 v1(3295.28,-196.85)
1V2_mon2: C203.2 IC3.P12 P7.17 R207.2 | length 4851
  Top Layer w4: C203.2@3259.84,-173.23 v1(3311.02,-173.23) 3338.58,-173.23 IC3.P12@3370.08,-141.73
  M2 w4: v1(2200.79,480.32) 2358.27,637.8 4468.5,637.8 4511.81,594.49 4511.81,362.2 4472.44,322.83 4224.41,322.83 3948.82,47.24 3842.52,47.24 3779.53,-15.75 3779.53,-78.74 3716.54,-141.73 3370.08,-141.73 3338.58,-173.23 v1(3311.02,-173.23)
  Bottom Layer w4: v1(2200.79,480.32) 2200.79,385.83 2271.65,314.96 2444.88,314.96 2480.31,350.39 P7.17@2480.31,472.44 ; v1(3311.02,-173.23) 3318.9,-181.1 R207.2@3318.9,-271.65
1V2_mon3: C204.2 IC3.P11 P7.18 R209.2 | length 4746.9
  Top Layer w4: v1(3330.71,-149.61) IC3.P11@3370.08,-110.24
  M2 w4: v1(2228.35,480.32) 2362.2,614.17 4464.57,614.17 4488.19,590.55 4488.19,377.95 4456.69,346.46 4222.93,346.46 4006.4,129.92 3838.58,129.92 3763.78,55.12 3763.78,-62.99 3716.54,-110.24 3370.08,-110.24 v1(3330.71,-149.61)
  Bottom Layer w4: v1(2228.35,480.32) 2228.35,381.89 2283.46,326.77 2440.94,326.77 2464.57,350.39 P7.18@2464.57,472.44 ; C204.2@3259.84,-173.23 3275.59,-173.23 3299.21,-149.61 v1(3330.71,-149.61) 3334.65,-153.54 3334.65,-216.53 3370.08,-251.97 R209.2@3370.08,-271.65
